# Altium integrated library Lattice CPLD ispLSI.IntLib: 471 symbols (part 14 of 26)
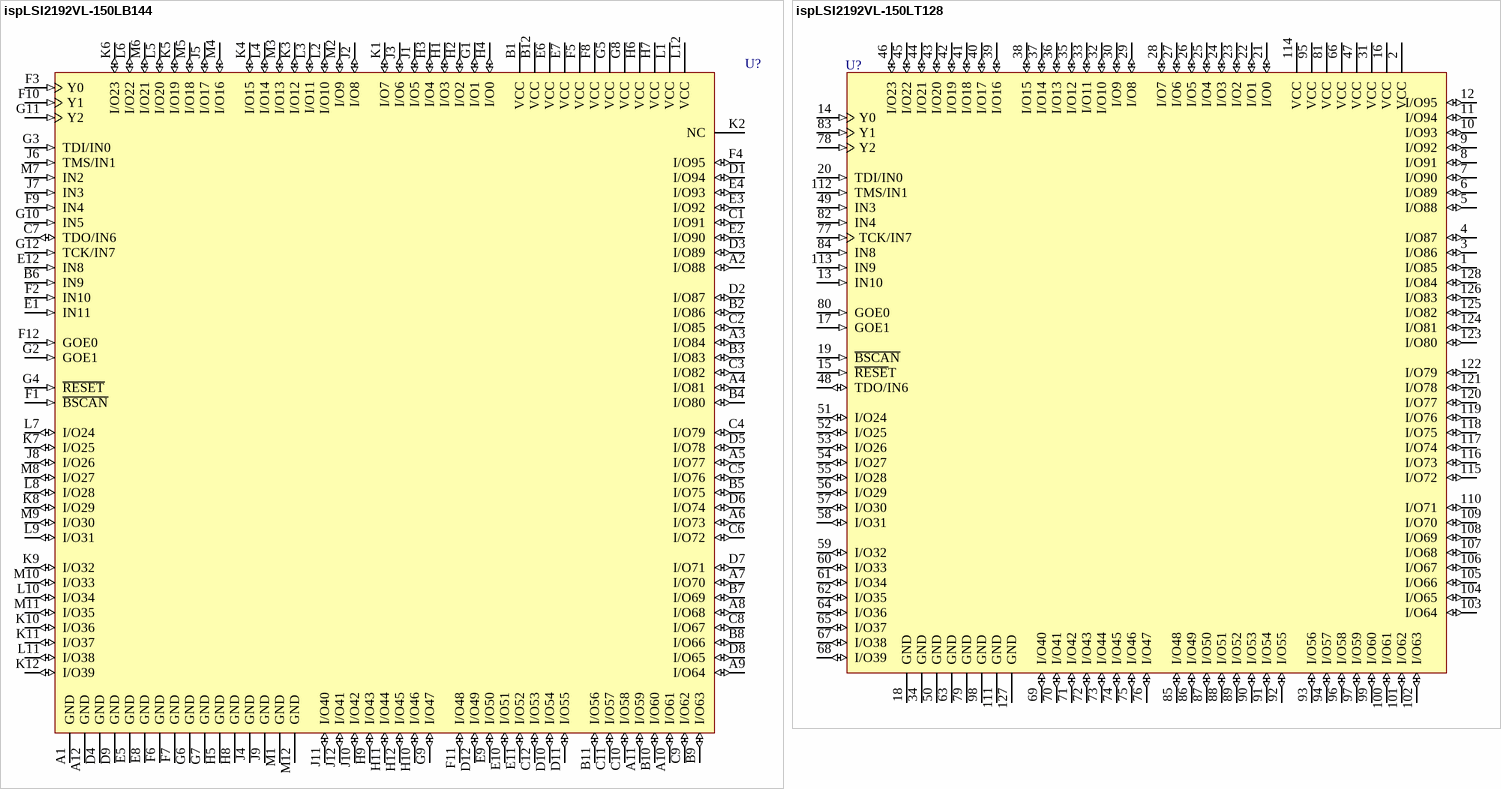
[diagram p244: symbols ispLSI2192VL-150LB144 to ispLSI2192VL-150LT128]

## ispLSI2192VL-150LB144
designator U?
2.5V In-System Programmable SuperFAST High Density PLD
footprint fpBGA144 (BGA, 144-Leads, Body 13x13mm, Pitch 1mm)
3D model 2192VL-fpBGA144 (144-Ball Fine Pitch Ball Grid Array (fpBGA144))
pins: A1 GND (power), A2 I/O88 (io), A3 I/O84 (io), A4 I/O81 (io), A5 I/O77 (io), A6 I/O73 (io), A7 I/O70 (io), A8 I/O68 (io), A9 I/O64 (io), A10 I/O61 (io), A11 I/O59 (io), A12 GND (power), B1 VCC (power), B2 I/O86 (io), B3 I/O83 (io), B4 I/O80 (io), B5 I/O75 (io), B6 IN9 (in), B7 I/O69 (io), B8 I/O66 (io), B9 I/O63 (io), B10 I/O60 (io), B11 I/O56 (io), B12 VCC (power), C1 I/O91 (io), C2 I/O85 (io), C3 I/O82 (io), C4 I/O79 (io), C5 I/O76 (io), C6 I/O72 (io), C7 TDO/IN6 (io), C8 I/O67 (io), C9 I/O62 (io), C10 I/O58 (io), C11 I/O57 (io), C12 I/O53 (io), D1 I/O94 (io), D2 I/O87 (io), D3 I/O89 (io), D4 GND (power), D5 I/O78 (io), D6 I/O74 (io), D7 I/O71 (io), D8 I/O65 (io), D9 GND (power), D10 I/O54 (io), D11 I/O55 (io), D12 I/O49 (io), E1 IN11 (in), E2 I/O90 (io), E3 I/O92 (io), E4 I/O93 (io), E5 GND (power), E6 VCC (power), E7 VCC (power), E8 GND (power), E9 I/O50 (io), E10 I/O51 (io), E11 I/O52 (io), E12 IN8 (in), F1 ~{BSCAN} (in), F2 IN10 (in), F3 Y0 (in), F4 I/O95 (io), F5 VCC (power), F6 GND (power), F7 GND (power), F8 VCC (power), F9 IN4 (in), F10 Y1 (in), F11 I/O48 (io), F12 GOE0 (in), G1 I/O1 (io), G2 GOE1 (in), G3 TDI/IN0 (in), G4 ~{RESET} (in), G5 VCC (power), G6 GND (power), G7 GND (power), G8 VCC (power), G9 I/O47 (io), G10 IN5 (in), G11 Y2 (in), G12 TCK/IN7 (in), H1 I/O3 (io), H2 I/O2 (io), H3 I/O4 (io), H4 I/O0 (io), H5 GND (power), H6 VCC (power), H7 VCC (power), H8 GND (power), H9 I/O43 (io), H10 I/O46 (io), H11 I/O44 (io), H12 I/O45 (io), J1 I/O5 (io), J2 I/O8 (io), J3 I/O6 (io), J4 GND (power), J5 I/O17 (io), J6 TMS/IN1 (in), J7 IN3 (in), J8 I/O26 (io), J9 GND (power), J10 I/O42 (io), J11 I/O40 (io), J12 I/O41 (io), K1 I/O7 (io), K2 NC, K3 I/O12 (io), K4 I/O15 (io), K5 I/O19 (io), K6 I/O23 (io), K7 I/O25 (io), K8 I/O29 (io), K9 I/O32 (io), K10 I/O36 (io), K11 I/O37 (io), K12 I/O39 (io), L1 VCC (power), L2 I/O10 (io), L3 I/O11 (io), L4 I/O14 (io), L5 I/O20 (io), L6 I/O22 (io), L7 I/O24 (io), L8 I/O28 (io), L9 I/O31 (io), L10 I/O34 (io), L11 I/O38 (io), L12 VCC (power), M1 GND (power), M2 I/O9 (io), M3 I/O13 (io), M4 I/O16 (io), M5 I/O18 (io), M6 I/O21 (io), M7 IN2 (in), M8 I/O27 (io), M9 I/O30 (io), M10 I/O33 (io), M11 I/O35 (io), M12 GND (power)

## ispLSI2192VL-150LT128
designator U?
2.5V In-System Programmable SuperFAST High Density PLD
footprint TQFP128_N (Thin QFP, 128-Leads, Body 14x14mm, Pitch 0.4mm, IPC Medium Density)
footprint TQFP128_L (Thin QFP, 128-Leads, Body 14x14mm, Pitch 0.4mm, IPC High Density)
footprint TQFP128_M (Thin QFP, 128-Leads, Body 14x14mm, Pitch 0.4mm, IPC Low Density)
3D model 2192VL-TQFP128 (128-Pin Thin Quad Flat Pack 0.4 mm Pitch)
pins: 1 I/O85 (io), 2 VCC (power), 3 I/O86 (io), 4 I/O87 (io), 5 I/O88 (io), 6 I/O89 (io), 7 I/O90 (io), 8 I/O91 (io), 9 I/O92 (io), 10 I/O93 (io), 11 I/O94 (io), 12 I/O95 (io), 13 IN10 (in), 14 Y0 (in), 15 ~{RESE}T (in), 16 VCC (power), 17 GOE1 (in), 18 GND (power), 19 ~{BSCAN} (in), 20 TDI/IN0 (in), 21 I/O0 (io), 22 I/O1 (io), 23 I/O2 (io), 24 I/O3 (io), 25 I/O4 (io), 26 I/O5 (io), 27 I/O6 (io), 28 I/O7 (io), 29 I/O8 (io), 30 I/O9 (io), 31 VCC (power), 32 I/O10 (io), 33 I/O11 (io), 34 GND (power), 35 I/O12 (io), 36 I/O13 (io), 37 I/O14 (io), 38 I/O15 (io), 39 I/O16 (io), 40 I/O17 (io), 41 I/O18 (io), 42 I/O19 (io), 43 I/O20 (io), 44 I/O21 (io), 45 I/O22 (io), 46 I/O23 (io), 47 VCC (power), 48 TDO/IN6 (io), 49 IN3 (in), 50 GND (power), 51 I/O24 (io), 52 I/O25 (io), 53 I/O26 (io), 54 I/O27 (io), 55 I/O28 (io), 56 I/O29 (io), 57 I/O30 (io), 58 I/O31 (io), 59 I/O32 (io), 60 I/O33 (io), 61 I/O34 (io), 62 I/O35 (io), 63 GND (power), 64 I/O36 (io), 65 I/O37 (io), 66 VCC (power), 67 I/O38 (io), 68 I/O39 (io), 69 I/O40 (io), 70 I/O41 (io), 71 I/O42 (io), 72 I/O43 (io), 73 I/O44 (io), 74 I/O45 (io), 75 I/O46 (io), 76 I/O47 (io), 77 TCK/IN7 (in), 78 Y2 (in), 79 GND (power), 80 GOE0 (in), 81 VCC (power), 82 IN4 (in), 83 Y1 (in), 84 IN8 (in), 85 I/O48 (io), 86 I/O49 (io), 87 I/O50 (io), 88 I/O51 (io), 89 I/O52 (io), 90 I/O53 (io), 91 I/O54 (io), 92 I/O55 (io), 93 I/O56 (io), 94 I/O57 (io), 95 VCC (power), 96 I/O58 (io), 97 I/O59 (io), 98 GND (power), 99 I/O60 (io), 100 I/O61 (io), 101 I/O62 (io), 102 I/O63 (io), 103 I/O64 (io), 104 I/O65 (io), 105 I/O66 (io), 106 I/O67 (io), 107 I/O68 (io), 108 I/O69 (io), 109 I/O70 (io), 110 I/O71 (io), 111 GND (power), 112 TMS/IN1 (in), 113 IN9 (in), 114 VCC (power), 115 I/O72 (io), 116 I/O73 (io), 117 I/O74 (io), 118 I/O75 (io), 119 I/O76 (io), 120 I/O77 (io), 121 I/O78 (io), 122 I/O79 (io), 123 I/O80 (io), 124 I/O81 (io), 125 I/O82 (io), 126 I/O83 (io), 127 GND (power), 128 I/O84 (io)

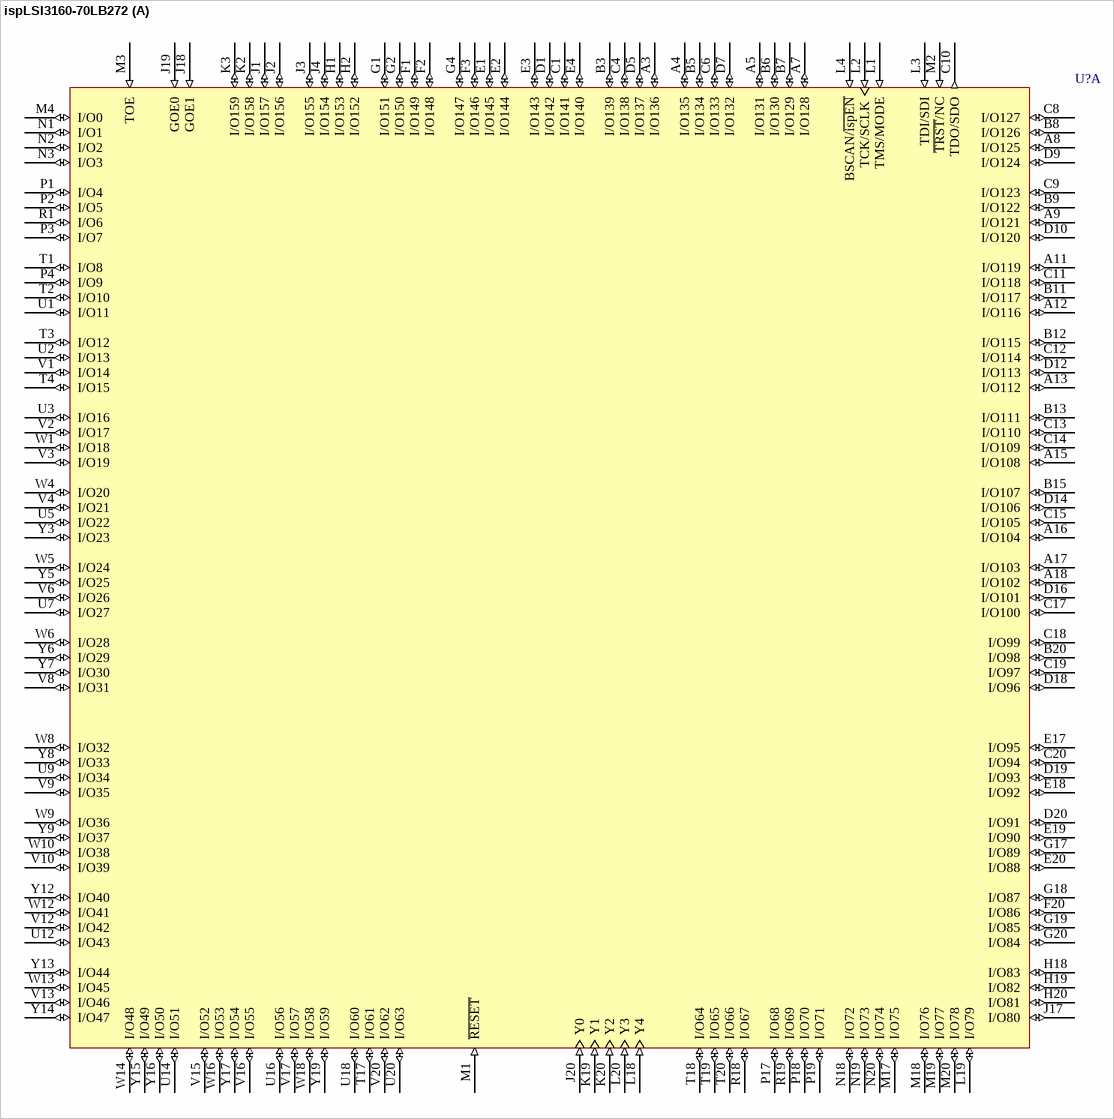
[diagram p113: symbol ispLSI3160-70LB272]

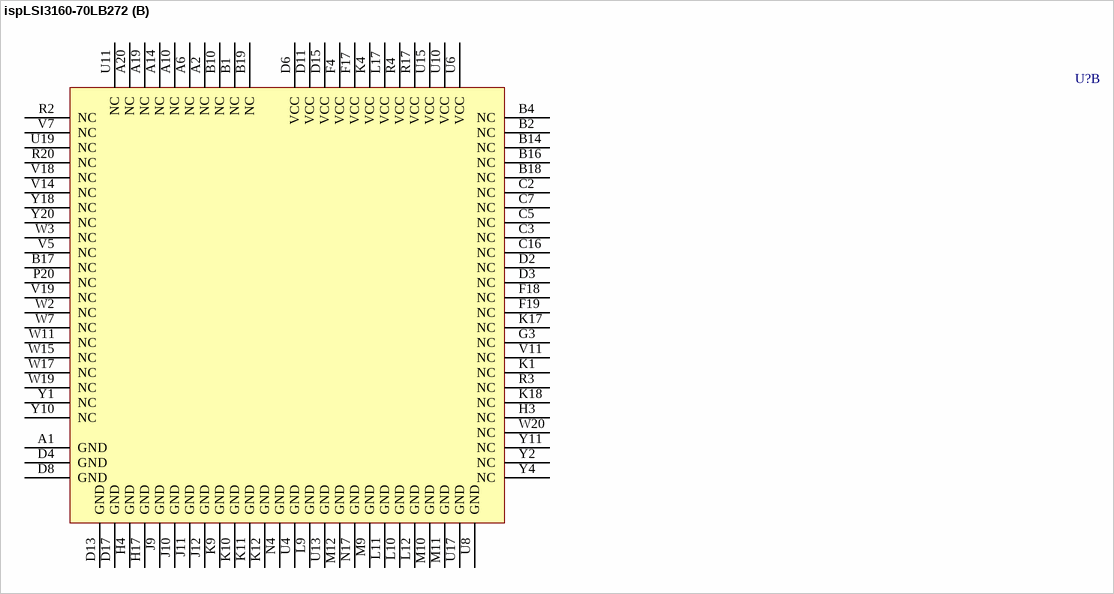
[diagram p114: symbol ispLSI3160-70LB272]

## ispLSI3160-70LB272
designator U?
In-System Programmable High-Density PLD
footprint BGA272 (BGA, 272-Leads, Body 27x27mm, Pitch 1.27mm)
3D model 3160-BGA272 (272-Ball Ball Grid Array (BGA272))
part A pins: A3 I/O136 (io), A4 I/O135 (io), A5 I/O131 (io), A7 I/O128 (io), A8 I/O125 (io), A9 I/O121 (io), A11 I/O119 (io), A12 I/O116 (io), A13 I/O112 (io), A15 I/O108 (io), A16 I/O104 (io), A17 I/O103 (io), A18 I/O102 (io), B3 I/O139 (io), B5 I/O134 (io), B6 I/O130 (io), B7 I/O129 (io), B8 I/O126 (io), B9 I/O122 (io), B11 I/O117 (io), B12 I/O115 (io), B13 I/O111 (io), B15 I/O107 (io), B20 I/O98 (io), C1 I/O141 (io), C4 I/O138 (io), C6 I/O133 (io), C8 I/O127 (io), C9 I/O123 (io), C10 TDO/SDO (out), C11 I/O118 (io), C12 I/O114 (io), C13 I/O110 (io), C14 I/O109 (io), C15 I/O105 (io), C17 I/O100 (io), C18 I/O99 (io), C19 I/O97 (io), C20 I/O94 (io), D1 I/O142 (io), D5 I/O137 (io), D7 I/O132 (io), D9 I/O124 (io), D10 I/O120 (io), D12 I/O113 (io), D14 I/O106 (io), D16 I/O101 (io), D18 I/O96 (io), D19 I/O93 (io), D20 I/O91 (io), E1 I/O145 (io), E2 I/O144 (io), E3 I/O143 (io), E4 I/O140 (io), E17 I/O95 (io), E18 I/O92 (io), E19 I/O90 (io), E20 I/O88 (io), F1 I/O149 (io), F2 I/O148 (io), F3 I/O146 (io), F20 I/O86 (io), G1 I/O151 (io), G2 I/O150 (io), G4 I/O147 (io), G17 I/O89 (io), G18 I/O87 (io), G19 I/O85 (io), G20 I/O84 (io), H1 I/O153 (io), H2 I/O152 (io), H18 I/O83 (io), H19 I/O82 (io), H20 I/O81 (io), J1 I/O157 (io), J2 I/O156 (io), J3 I/O155 (io), J4 I/O154 (io), J17 I/O80 (io), J18 GOE1 (in), J19 GOE0 (in), J20 Y0 (in), K2 I/O158 (io), K3 I/O159 (io), K19 Y1 (in), K20 Y2 (in), L1 TMS/MODE (in), L2 TCK/SCLK (in), L3 TDI/SDI (in), L4 BSCAN/~{ispEN} (in), L18 Y4 (in), L19 I/O79 (io), L20 Y3 (in), M1 ~{RESET} (in), M2 ~{TRST}/NC (in), M3 TOE (in), M4 I/O0 (io), M17 I/O75 (io), M18 I/O76 (io), M19 I/O77 (io), M20 I/O78 (io), N1 I/O1 (io), N2 I/O2 (io), N3 I/O3 (io), N18 I/O72 (io), N19 I/O73 (io), N20 I/O74 (io), P1 I/O4 (io), P2 I/O5 (io), P3 I/O7 (io), P4 I/O9 (io), P17 I/O68 (io), P18 I/O70 (io), P19 I/O71 (io), R1 I/O6 (io), R18 I/O67 (io), R19 I/O69 (io), T1 I/O8 (io), T2 I/O10 (io), T3 I/O12 (io), T4 I/O15 (io), T17 I/O61 (io), T18 I/O64 (io), T19 I/O65 (io), T20 I/O66 (io), U1 I/O11 (io), U2 I/O13 (io), U3 I/O16 (io), U5 I/O22 (io), U7 I/O27 (io), U9 I/O34 (io), U12 I/O43 (io), U14 I/O51 (io), U16 I/O56 (io), U18 I/O60 (io), U20 I/O63 (io), V1 I/O14 (io), V2 I/O17 (io), V3 I/O19 (io), V4 I/O21 (io), V6 I/O26 (io), V8 I/O31 (io), V9 I/O35 (io), V10 I/O39 (io), V12 I/O42 (io), V13 I/O46 (io), V15 I/O52 (io), V16 I/O55 (io), V17 I/O57 (io), V20 I/O62 (io), W1 I/O18 (io), W4 I/O20 (io), W5 I/O24 (io), W6 I/O28 (io), W8 I/O32 (io), W9 I/O36 (io), W10 I/O38 (io), W12 I/O41 (io), W13 I/O45 (io), W14 I/O48 (io), W16 I/O53 (io), W18 I/O58 (io), Y3 I/O23 (io), Y5 I/O25 (io), Y6 I/O29 (io), Y7 I/O30 (io), Y8 I/O33 (io), Y9 I/O37 (io), Y12 I/O40 (io), Y13 I/O44 (io), Y14 I/O47 (io), Y15 I/O49 (io), Y16 I/O50 (io), Y17 I/O54 (io), Y19 I/O59 (io)
part B pins: A1 GND (power), A2 NC, A6 NC, A10 NC, A14 NC, A19 NC, A20 NC, B1 NC, B2 NC, B4 NC, B10 NC, B14 NC, B16 NC, B17 NC, B18 NC, B19 NC, C2 NC, C3 NC, C5 NC, C7 NC, C16 NC, D2 NC, D3 NC, D4 GND (power), D6 VCC (power), D8 GND (power), D11 VCC (power), D13 GND (power), D15 VCC (power), D17 GND (power), F4 VCC (power), F17 VCC (power), F18 NC, F19 NC, G3 NC, H3 NC, H4 GND (power), H17 GND (power), J9 GND (power), J10 GND (power), J11 GND (power), J12 GND (power), K1 NC, K4 VCC (power), K9 GND (power), K10 GND (power), K11 GND (power), K12 GND (power), K17 NC, K18 NC, L9 GND (power), L10 GND (power), L11 GND (power), L12 GND (power), L17 VCC (power), M9 GND (power), M10 GND (power), M11 GND (power), M12 GND (power), N4 GND (power), N17 GND (power), P20 NC, R2 NC, R3 NC, R4 VCC (power), R17 VCC (power), R20 NC, U4 GND (power), U6 VCC (power), U8 GND (power), U10 VCC (power), U11 NC, U13 GND (power), U15 VCC (power), U17 GND (power), U19 NC, V5 NC, V7 NC, V11 NC, V14 NC, V18 NC, V19 NC, W2 NC, W3 NC, W7 NC, W11 NC, W15 NC, W17 NC, W19 NC, W20 NC, Y1 NC, Y2 NC, Y4 NC, Y10 NC, Y11 NC, Y18 NC, Y20 NC

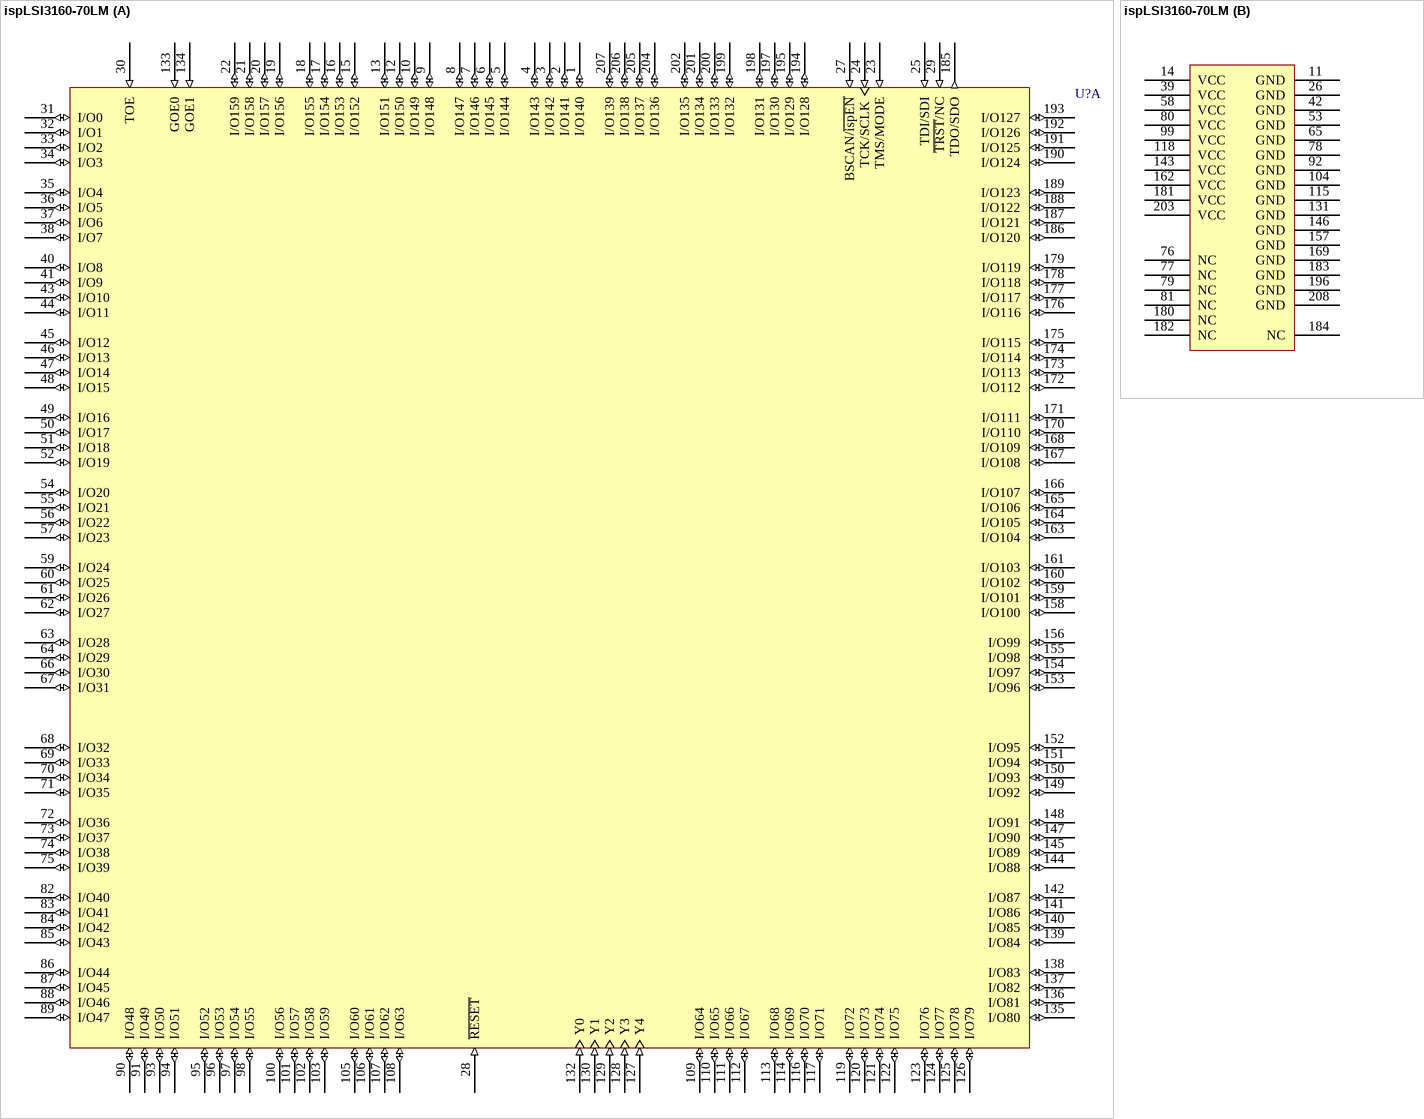
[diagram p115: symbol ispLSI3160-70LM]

## ispLSI3160-70LM
designator U?
In-System Programmable High-Density PLD
footprint MQFP208_N (Shrink QFP, 208-Leads, Body 27.7x27.7mm, Pitch 0.5mm, IPC Medium Density)
footprint MQFP208_L (Shrink QFP, 208-Leads, Body 27.7x27.7mm, Pitch 0.5mm, IPC High Density)
footprint MQFP208_M (Shrink QFP, 208-Leads, Body 27.7x27.7mm, Pitch 0.5mm, IPC Low Density)
3D model 3160-MQFP208 (208-Pin Shrink Quad Flat Pack 0.5 mm Pitch)
part A pins: 1 I/O140 (io), 2 I/O141 (io), 3 I/O142 (io), 4 I/O143 (io), 5 I/O144 (io), 6 I/O145 (io), 7 I/O146 (io), 8 I/O147 (io), 9 I/O148 (io), 10 I/O149 (io), 12 I/O150 (io), 13 I/O151 (io), 15 I/O152 (io), 16 I/O153 (io), 17 I/O154 (io), 18 I/O155 (io), 19 I/O156 (io), 20 I/O157 (io), 21 I/O158 (io), 22 I/O159 (io), 23 TMS/MODE (in), 24 TCK/SCLK (in), 25 TDI/SDI (in), 27 BSCAN/~{ispEN} (in), 28 ~{RESET} (in), 29 ~{TRST}/NC (in), 30 TOE (in), 31 I/O0 (io), 32 I/O1 (io), 33 I/O2 (io), 34 I/O3 (io), 35 I/O4 (io), 36 I/O5 (io), 37 I/O6 (io), 38 I/O7 (io), 40 I/O8 (io), 41 I/O9 (io), 43 I/O10 (io), 44 I/O11 (io), 45 I/O12 (io), 46 I/O13 (io), 47 I/O14 (io), 48 I/O15 (io), 49 I/O16 (io), 50 I/O17 (io), 51 I/O18 (io), 52 I/O19 (io), 54 I/O20 (io), 55 I/O21 (io), 56 I/O22 (io), 57 I/O23 (io), 59 I/O24 (io), 60 I/O25 (io), 61 I/O26 (io), 62 I/O27 (io), 63 I/O28 (io), 64 I/O29 (io), 66 I/O30 (io), 67 I/O31 (io), 68 I/O32 (io), 69 I/O33 (io), 70 I/O34 (io), 71 I/O35 (io), 72 I/O36 (io), 73 I/O37 (io), 74 I/O38 (io), 75 I/O39 (io), 82 I/O40 (io), 83 I/O41 (io), 84 I/O42 (io), 85 I/O43 (io), 86 I/O44 (io), 87 I/O45 (io), 88 I/O46 (io), 89 I/O47 (io), 90 I/O48 (io), 91 I/O49 (io), 93 I/O50 (io), 94 I/O51 (io), 95 I/O52 (io), 96 I/O53 (io), 97 I/O54 (io), 98 I/O55 (io), 100 I/O56 (io), 101 I/O57 (io), 102 I/O58 (io), 103 I/O59 (io), 105 I/O60 (io), 106 I/O61 (io), 107 I/O62 (io), 108 I/O63 (io), 109 I/O64 (io), 110 I/O65 (io), 111 I/O66 (io), 112 I/O67 (io), 113 I/O68 (io), 114 I/O69 (io), 116 I/O70 (io), 117 I/O71 (io), 119 I/O72 (io), 120 I/O73 (io), 121 I/O74 (io), 122 I/O75 (io), 123 I/O76 (io), 124 I/O77 (io), 125 I/O78 (io), 126 I/O79 (io), 127 Y4 (in), 128 Y3 (in), 129 Y2 (in), 130 Y1 (in), 132 Y0 (in), 133 GOE0 (in), 134 GOE1 (in), 135 I/O80 (io), 136 I/O81 (io), 137 I/O82 (io), 138 I/O83 (io), 139 I/O84 (io), 140 I/O85 (io), 141 I/O86 (io), 142 I/O87 (io), 144 I/O88 (io), 145 I/O89 (io), 147 I/O90 (io), 148 I/O91 (io), 149 I/O92 (io), 150 I/O93 (io), 151 I/O94 (io), 152 I/O95 (io), 153 I/O96 (io), 154 I/O97 (io), 155 I/O98 (io), 156 I/O99 (io), 158 I/O100 (io), 159 I/O101 (io), 160 I/O102 (io), 161 I/O103 (io), 163 I/O104 (io), 164 I/O105 (io), 165 I/O106 (io), 166 I/O107 (io), 167 I/O108 (io), 168 I/O109 (io), 170 I/O110 (io), 171 I/O111 (io), 172 I/O112 (io), 173 I/O113 (io), 174 I/O114 (io), 175 I/O115 (io), 176 I/O116 (io), 177 I/O117 (io), 178 I/O118 (io), 179 I/O119 (io), 185 TDO/SDO (out), 186 I/O120 (io), 187 I/O121 (io), 188 I/O122 (io), 189 I/O123 (io), 190 I/O124 (io), 191 I/O125 (io), 192 I/O126 (io), 193 I/O127 (io), 194 I/O128 (io), 195 I/O129 (io), 197 I/O130 (io), 198 I/O131 (io), 199 I/O132 (io), 200 I/O133 (io), 201 I/O134 (io), 202 I/O135 (io), 204 I/O136 (io), 205 I/O137 (io), 206 I/O138 (io), 207 I/O139 (io)
part B pins: 11 GND (power), 14 VCC (power), 26 GND (power), 39 VCC (power), 42 GND (power), 53 GND (power), 58 VCC (power), 65 GND (power), 76 NC, 77 NC, 78 GND (power), 79 NC, 80 VCC (power), 81 NC, 92 GND (power), 99 VCC (power), 104 GND (power), 115 GND (power), 118 VCC (power), 131 GND (power), 143 VCC (power), 146 GND (power), 157 GND (power), 162 VCC (power), 169 GND (power), 180 NC, 181 VCC (power), 182 NC, 183 GND (power), 184 NC, 196 GND (power), 203 VCC (power), 208 GND (power)

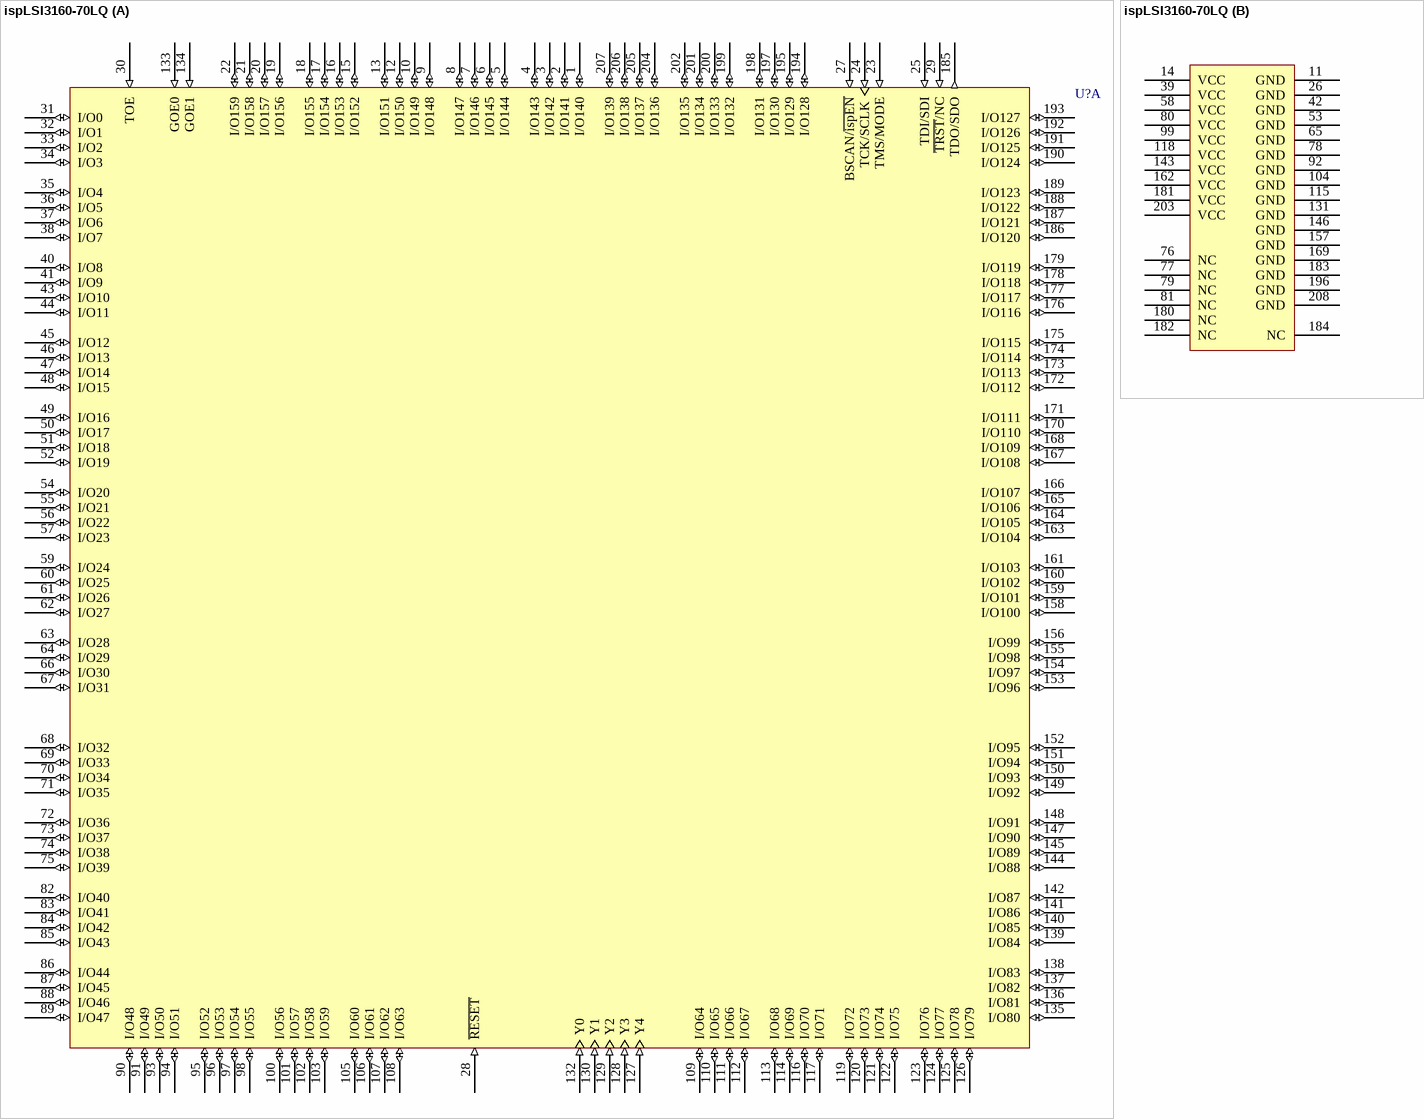
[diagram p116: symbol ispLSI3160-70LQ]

## ispLSI3160-70LQ
designator U?
In-System Programmable High-Density PLD
footprint PQFP208_N (Shrink QFP, 208-Leads, Body 28x28mm, Pitch 0.5mm, IPC Medium Density)
footprint PQFP208_L (Shrink QFP, 208-Leads, Body 28x28mm, Pitch 0.5mm, IPC High Density)
footprint PQFP208_M (Shrink QFP, 208-Leads, Body 28x28mm, Pitch 0.5mm, IPC Low Density)
3D model 3160-PQFP208 (208-Pin Plastic Quad Flat Pack (PQFP208))
part A pins: 1 I/O140 (io), 2 I/O141 (io), 3 I/O142 (io), 4 I/O143 (io), 5 I/O144 (io), 6 I/O145 (io), 7 I/O146 (io), 8 I/O147 (io), 9 I/O148 (io), 10 I/O149 (io), 12 I/O150 (io), 13 I/O151 (io), 15 I/O152 (io), 16 I/O153 (io), 17 I/O154 (io), 18 I/O155 (io), 19 I/O156 (io), 20 I/O157 (io), 21 I/O158 (io), 22 I/O159 (io), 23 TMS/MODE (in), 24 TCK/SCLK (in), 25 TDI/SDI (in), 27 BSCAN/~{ispEN} (in), 28 ~{RESET} (in), 29 ~{TRST}/NC (in), 30 TOE (in), 31 I/O0 (io), 32 I/O1 (io), 33 I/O2 (io), 34 I/O3 (io), 35 I/O4 (io), 36 I/O5 (io), 37 I/O6 (io), 38 I/O7 (io), 40 I/O8 (io), 41 I/O9 (io), 43 I/O10 (io), 44 I/O11 (io), 45 I/O12 (io), 46 I/O13 (io), 47 I/O14 (io), 48 I/O15 (io), 49 I/O16 (io), 50 I/O17 (io), 51 I/O18 (io), 52 I/O19 (io), 54 I/O20 (io), 55 I/O21 (io), 56 I/O22 (io), 57 I/O23 (io), 59 I/O24 (io), 60 I/O25 (io), 61 I/O26 (io), 62 I/O27 (io), 63 I/O28 (io), 64 I/O29 (io), 66 I/O30 (io), 67 I/O31 (io), 68 I/O32 (io), 69 I/O33 (io), 70 I/O34 (io), 71 I/O35 (io), 72 I/O36 (io), 73 I/O37 (io), 74 I/O38 (io), 75 I/O39 (io), 82 I/O40 (io), 83 I/O41 (io), 84 I/O42 (io), 85 I/O43 (io), 86 I/O44 (io), 87 I/O45 (io), 88 I/O46 (io), 89 I/O47 (io), 90 I/O48 (io), 91 I/O49 (io), 93 I/O50 (io), 94 I/O51 (io), 95 I/O52 (io), 96 I/O53 (io), 97 I/O54 (io), 98 I/O55 (io), 100 I/O56 (io), 101 I/O57 (io), 102 I/O58 (io), 103 I/O59 (io), 105 I/O60 (io), 106 I/O61 (io), 107 I/O62 (io), 108 I/O63 (io), 109 I/O64 (io), 110 I/O65 (io), 111 I/O66 (io), 112 I/O67 (io), 113 I/O68 (io), 114 I/O69 (io), 116 I/O70 (io), 117 I/O71 (io), 119 I/O72 (io), 120 I/O73 (io), 121 I/O74 (io), 122 I/O75 (io), 123 I/O76 (io), 124 I/O77 (io), 125 I/O78 (io), 126 I/O79 (io), 127 Y4 (in), 128 Y3 (in), 129 Y2 (in), 130 Y1 (in), 132 Y0 (in), 133 GOE0 (in), 134 GOE1 (in), 135 I/O80 (io), 136 I/O81 (io), 137 I/O82 (io), 138 I/O83 (io), 139 I/O84 (io), 140 I/O85 (io), 141 I/O86 (io), 142 I/O87 (io), 144 I/O88 (io), 145 I/O89 (io), 147 I/O90 (io), 148 I/O91 (io), 149 I/O92 (io), 150 I/O93 (io), 151 I/O94 (io), 152 I/O95 (io), 153 I/O96 (io), 154 I/O97 (io), 155 I/O98 (io), 156 I/O99 (io), 158 I/O100 (io), 159 I/O101 (io), 160 I/O102 (io), 161 I/O103 (io), 163 I/O104 (io), 164 I/O105 (io), 165 I/O106 (io), 166 I/O107 (io), 167 I/O108 (io), 168 I/O109 (io), 170 I/O110 (io), 171 I/O111 (io), 172 I/O112 (io), 173 I/O113 (io), 174 I/O114 (io), 175 I/O115 (io), 176 I/O116 (io), 177 I/O117 (io), 178 I/O118 (io), 179 I/O119 (io), 185 TDO/SDO (out), 186 I/O120 (io), 187 I/O121 (io), 188 I/O122 (io), 189 I/O123 (io), 190 I/O124 (io), 191 I/O125 (io), 192 I/O126 (io), 193 I/O127 (io), 194 I/O128 (io), 195 I/O129 (io), 197 I/O130 (io), 198 I/O131 (io), 199 I/O132 (io), 200 I/O133 (io), 201 I/O134 (io), 202 I/O135 (io), 204 I/O136 (io), 205 I/O137 (io), 206 I/O138 (io), 207 I/O139 (io)
part B pins: 11 GND (power), 14 VCC (power), 26 GND (power), 39 VCC (power), 42 GND (power), 53 GND (power), 58 VCC (power), 65 GND (power), 76 NC, 77 NC, 78 GND (power), 79 NC, 80 VCC (power), 81 NC, 92 GND (power), 99 VCC (power), 104 GND (power), 115 GND (power), 118 VCC (power), 131 GND (power), 143 VCC (power), 146 GND (power), 157 GND (power), 162 VCC (power), 169 GND (power), 180 NC, 181 VCC (power), 182 NC, 183 GND (power), 184 NC, 196 GND (power), 203 VCC (power), 208 GND (power)

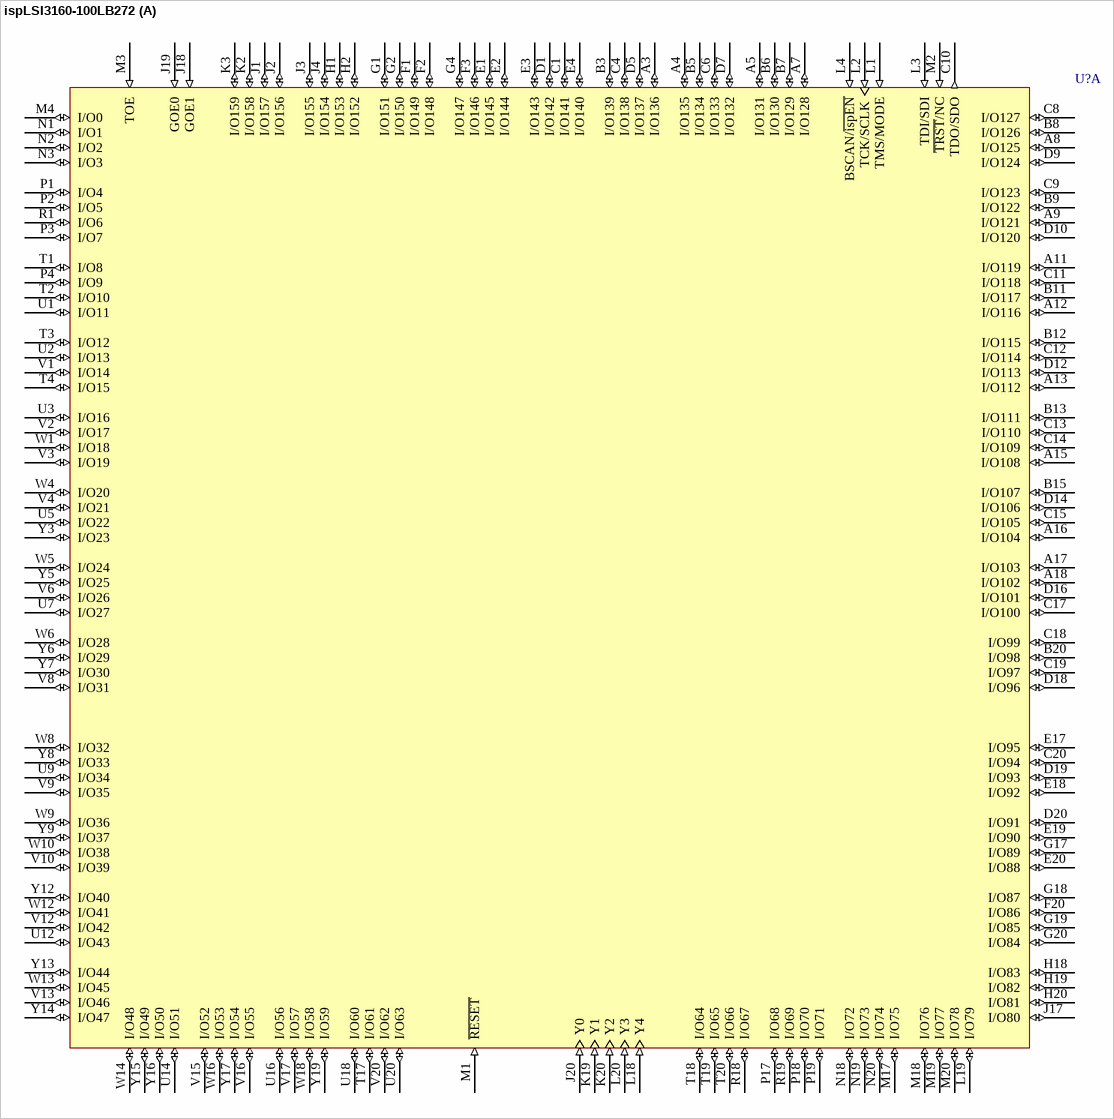
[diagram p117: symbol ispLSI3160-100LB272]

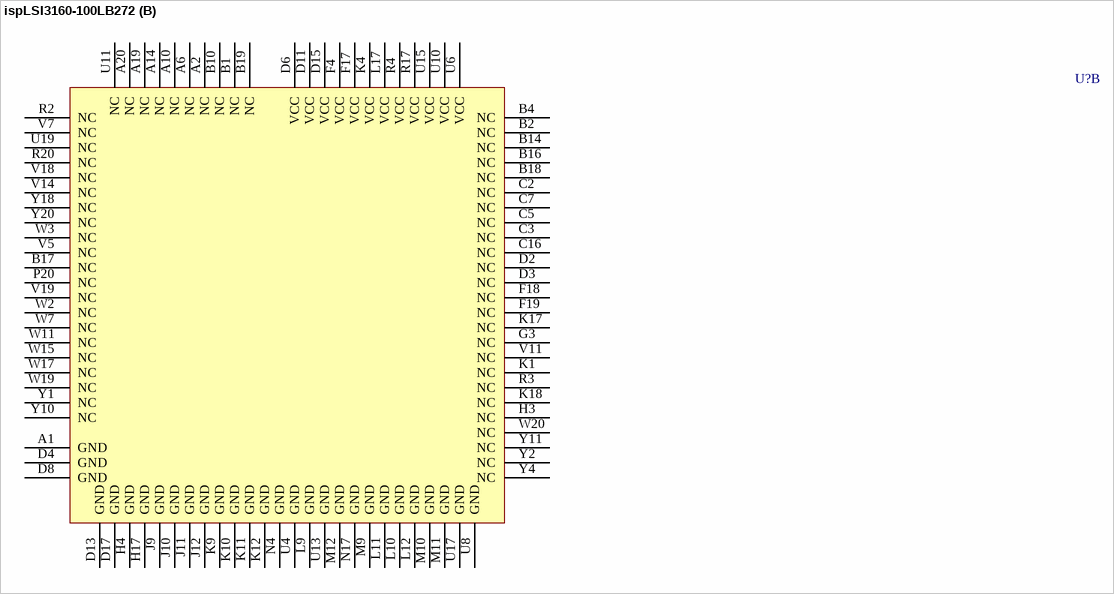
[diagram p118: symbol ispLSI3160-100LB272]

## ispLSI3160-100LB272
designator U?
In-System Programmable High-Density PLD
footprint BGA272 (BGA, 272-Leads, Body 27x27mm, Pitch 1.27mm)
3D model 3160-BGA272 (272-Ball Ball Grid Array (BGA272))
part A pins: A3 I/O136 (io), A4 I/O135 (io), A5 I/O131 (io), A7 I/O128 (io), A8 I/O125 (io), A9 I/O121 (io), A11 I/O119 (io), A12 I/O116 (io), A13 I/O112 (io), A15 I/O108 (io), A16 I/O104 (io), A17 I/O103 (io), A18 I/O102 (io), B3 I/O139 (io), B5 I/O134 (io), B6 I/O130 (io), B7 I/O129 (io), B8 I/O126 (io), B9 I/O122 (io), B11 I/O117 (io), B12 I/O115 (io), B13 I/O111 (io), B15 I/O107 (io), B20 I/O98 (io), C1 I/O141 (io), C4 I/O138 (io), C6 I/O133 (io), C8 I/O127 (io), C9 I/O123 (io), C10 TDO/SDO (out), C11 I/O118 (io), C12 I/O114 (io), C13 I/O110 (io), C14 I/O109 (io), C15 I/O105 (io), C17 I/O100 (io), C18 I/O99 (io), C19 I/O97 (io), C20 I/O94 (io), D1 I/O142 (io), D5 I/O137 (io), D7 I/O132 (io), D9 I/O124 (io), D10 I/O120 (io), D12 I/O113 (io), D14 I/O106 (io), D16 I/O101 (io), D18 I/O96 (io), D19 I/O93 (io), D20 I/O91 (io), E1 I/O145 (io), E2 I/O144 (io), E3 I/O143 (io), E4 I/O140 (io), E17 I/O95 (io), E18 I/O92 (io), E19 I/O90 (io), E20 I/O88 (io), F1 I/O149 (io), F2 I/O148 (io), F3 I/O146 (io), F20 I/O86 (io), G1 I/O151 (io), G2 I/O150 (io), G4 I/O147 (io), G17 I/O89 (io), G18 I/O87 (io), G19 I/O85 (io), G20 I/O84 (io), H1 I/O153 (io), H2 I/O152 (io), H18 I/O83 (io), H19 I/O82 (io), H20 I/O81 (io), J1 I/O157 (io), J2 I/O156 (io), J3 I/O155 (io), J4 I/O154 (io), J17 I/O80 (io), J18 GOE1 (in), J19 GOE0 (in), J20 Y0 (in), K2 I/O158 (io), K3 I/O159 (io), K19 Y1 (in), K20 Y2 (in), L1 TMS/MODE (in), L2 TCK/SCLK (in), L3 TDI/SDI (in), L4 BSCAN/~{ispEN} (in), L18 Y4 (in), L19 I/O79 (io), L20 Y3 (in), M1 ~{RESET} (in), M2 ~{TRST}/NC (in), M3 TOE (in), M4 I/O0 (io), M17 I/O75 (io), M18 I/O76 (io), M19 I/O77 (io), M20 I/O78 (io), N1 I/O1 (io), N2 I/O2 (io), N3 I/O3 (io), N18 I/O72 (io), N19 I/O73 (io), N20 I/O74 (io), P1 I/O4 (io), P2 I/O5 (io), P3 I/O7 (io), P4 I/O9 (io), P17 I/O68 (io), P18 I/O70 (io), P19 I/O71 (io), R1 I/O6 (io), R18 I/O67 (io), R19 I/O69 (io), T1 I/O8 (io), T2 I/O10 (io), T3 I/O12 (io), T4 I/O15 (io), T17 I/O61 (io), T18 I/O64 (io), T19 I/O65 (io), T20 I/O66 (io), U1 I/O11 (io), U2 I/O13 (io), U3 I/O16 (io), U5 I/O22 (io), U7 I/O27 (io), U9 I/O34 (io), U12 I/O43 (io), U14 I/O51 (io), U16 I/O56 (io), U18 I/O60 (io), U20 I/O63 (io), V1 I/O14 (io), V2 I/O17 (io), V3 I/O19 (io), V4 I/O21 (io), V6 I/O26 (io), V8 I/O31 (io), V9 I/O35 (io), V10 I/O39 (io), V12 I/O42 (io), V13 I/O46 (io), V15 I/O52 (io), V16 I/O55 (io), V17 I/O57 (io), V20 I/O62 (io), W1 I/O18 (io), W4 I/O20 (io), W5 I/O24 (io), W6 I/O28 (io), W8 I/O32 (io), W9 I/O36 (io), W10 I/O38 (io), W12 I/O41 (io), W13 I/O45 (io), W14 I/O48 (io), W16 I/O53 (io), W18 I/O58 (io), Y3 I/O23 (io), Y5 I/O25 (io), Y6 I/O29 (io), Y7 I/O30 (io), Y8 I/O33 (io), Y9 I/O37 (io), Y12 I/O40 (io), Y13 I/O44 (io), Y14 I/O47 (io), Y15 I/O49 (io), Y16 I/O50 (io), Y17 I/O54 (io), Y19 I/O59 (io)
part B pins: A1 GND (power), A2 NC, A6 NC, A10 NC, A14 NC, A19 NC, A20 NC, B1 NC, B2 NC, B4 NC, B10 NC, B14 NC, B16 NC, B17 NC, B18 NC, B19 NC, C2 NC, C3 NC, C5 NC, C7 NC, C16 NC, D2 NC, D3 NC, D4 GND (power), D6 VCC (power), D8 GND (power), D11 VCC (power), D13 GND (power), D15 VCC (power), D17 GND (power), F4 VCC (power), F17 VCC (power), F18 NC, F19 NC, G3 NC, H3 NC, H4 GND (power), H17 GND (power), J9 GND (power), J10 GND (power), J11 GND (power), J12 GND (power), K1 NC, K4 VCC (power), K9 GND (power), K10 GND (power), K11 GND (power), K12 GND (power), K17 NC, K18 NC, L9 GND (power), L10 GND (power), L11 GND (power), L12 GND (power), L17 VCC (power), M9 GND (power), M10 GND (power), M11 GND (power), M12 GND (power), N4 GND (power), N17 GND (power), P20 NC, R2 NC, R3 NC, R4 VCC (power), R17 VCC (power), R20 NC, U4 GND (power), U6 VCC (power), U8 GND (power), U10 VCC (power), U11 NC, U13 GND (power), U15 VCC (power), U17 GND (power), U19 NC, V5 NC, V7 NC, V11 NC, V14 NC, V18 NC, V19 NC, W2 NC, W3 NC, W7 NC, W11 NC, W15 NC, W17 NC, W19 NC, W20 NC, Y1 NC, Y2 NC, Y4 NC, Y10 NC, Y11 NC, Y18 NC, Y20 NC

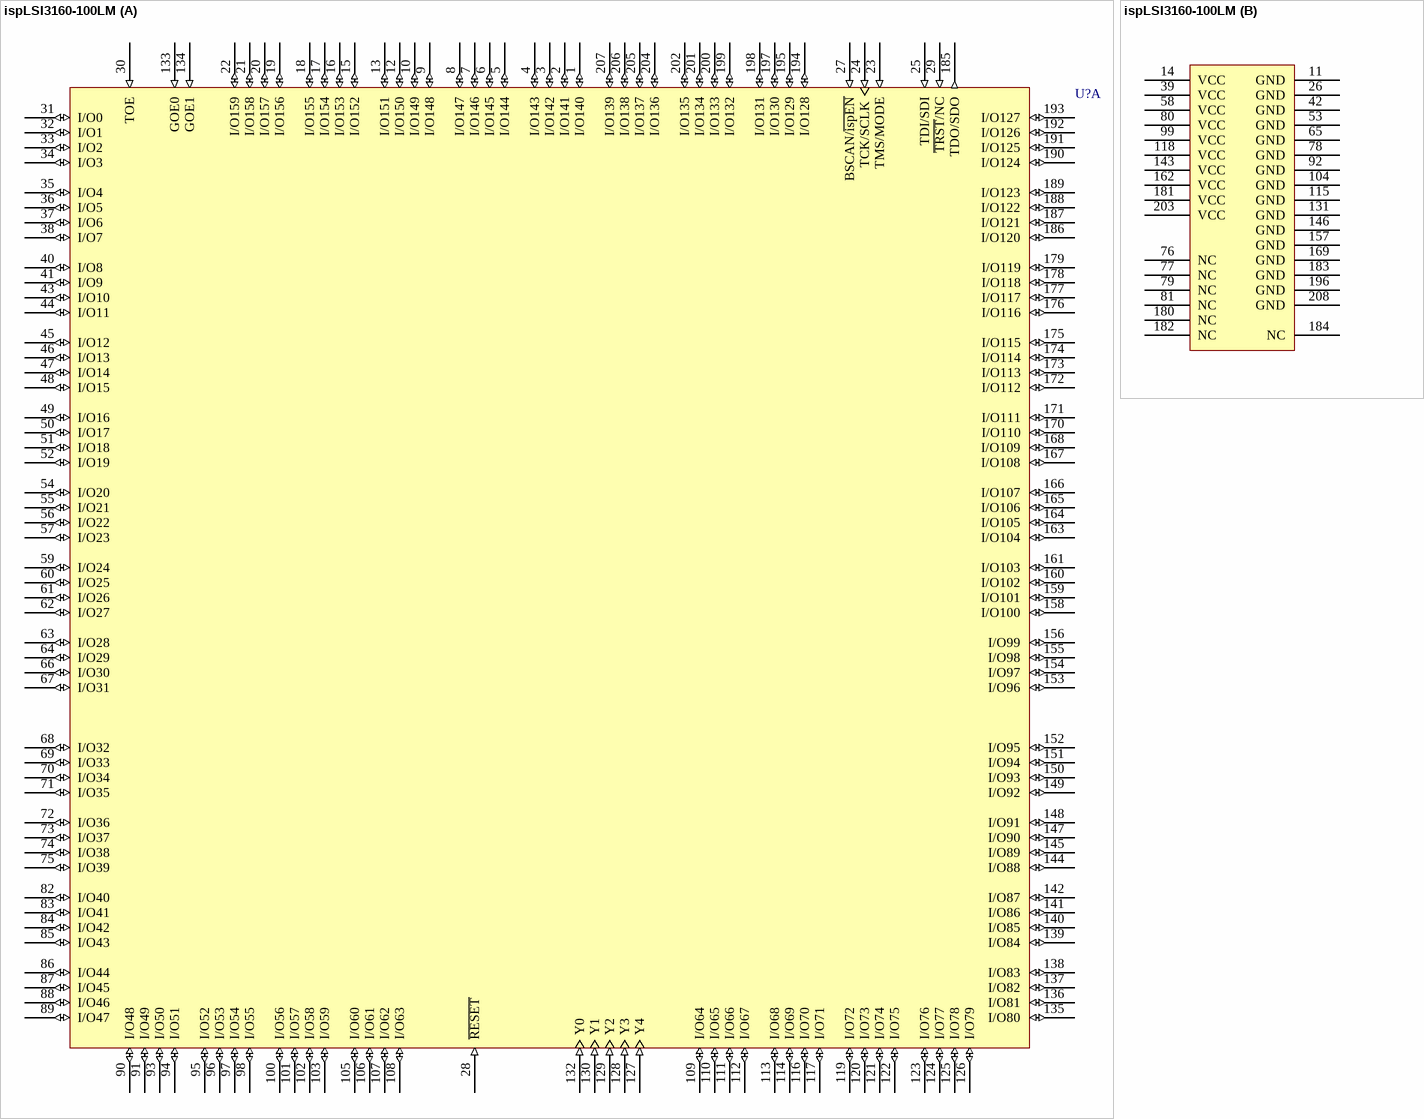
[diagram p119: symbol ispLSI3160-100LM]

## ispLSI3160-100LM
designator U?
In-System Programmable High-Density PLD
footprint MQFP208_N (Shrink QFP, 208-Leads, Body 27.7x27.7mm, Pitch 0.5mm, IPC Medium Density)
footprint MQFP208_L (Shrink QFP, 208-Leads, Body 27.7x27.7mm, Pitch 0.5mm, IPC High Density)
footprint MQFP208_M (Shrink QFP, 208-Leads, Body 27.7x27.7mm, Pitch 0.5mm, IPC Low Density)
3D model 3160-MQFP208 (208-Pin Shrink Quad Flat Pack 0.5 mm Pitch)
part A pins: 1 I/O140 (io), 2 I/O141 (io), 3 I/O142 (io), 4 I/O143 (io), 5 I/O144 (io), 6 I/O145 (io), 7 I/O146 (io), 8 I/O147 (io), 9 I/O148 (io), 10 I/O149 (io), 12 I/O150 (io), 13 I/O151 (io), 15 I/O152 (io), 16 I/O153 (io), 17 I/O154 (io), 18 I/O155 (io), 19 I/O156 (io), 20 I/O157 (io), 21 I/O158 (io), 22 I/O159 (io), 23 TMS/MODE (in), 24 TCK/SCLK (in), 25 TDI/SDI (in), 27 BSCAN/~{ispEN} (in), 28 ~{RESET} (in), 29 ~{TRST}/NC (in), 30 TOE (in), 31 I/O0 (io), 32 I/O1 (io), 33 I/O2 (io), 34 I/O3 (io), 35 I/O4 (io), 36 I/O5 (io), 37 I/O6 (io), 38 I/O7 (io), 40 I/O8 (io), 41 I/O9 (io), 43 I/O10 (io), 44 I/O11 (io), 45 I/O12 (io), 46 I/O13 (io), 47 I/O14 (io), 48 I/O15 (io), 49 I/O16 (io), 50 I/O17 (io), 51 I/O18 (io), 52 I/O19 (io), 54 I/O20 (io), 55 I/O21 (io), 56 I/O22 (io), 57 I/O23 (io), 59 I/O24 (io), 60 I/O25 (io), 61 I/O26 (io), 62 I/O27 (io), 63 I/O28 (io), 64 I/O29 (io), 66 I/O30 (io), 67 I/O31 (io), 68 I/O32 (io), 69 I/O33 (io), 70 I/O34 (io), 71 I/O35 (io), 72 I/O36 (io), 73 I/O37 (io), 74 I/O38 (io), 75 I/O39 (io), 82 I/O40 (io), 83 I/O41 (io), 84 I/O42 (io), 85 I/O43 (io), 86 I/O44 (io), 87 I/O45 (io), 88 I/O46 (io), 89 I/O47 (io), 90 I/O48 (io), 91 I/O49 (io), 93 I/O50 (io), 94 I/O51 (io), 95 I/O52 (io), 96 I/O53 (io), 97 I/O54 (io), 98 I/O55 (io), 100 I/O56 (io), 101 I/O57 (io), 102 I/O58 (io), 103 I/O59 (io), 105 I/O60 (io), 106 I/O61 (io), 107 I/O62 (io), 108 I/O63 (io), 109 I/O64 (io), 110 I/O65 (io), 111 I/O66 (io), 112 I/O67 (io), 113 I/O68 (io), 114 I/O69 (io), 116 I/O70 (io), 117 I/O71 (io), 119 I/O72 (io), 120 I/O73 (io), 121 I/O74 (io), 122 I/O75 (io), 123 I/O76 (io), 124 I/O77 (io), 125 I/O78 (io), 126 I/O79 (io), 127 Y4 (in), 128 Y3 (in), 129 Y2 (in), 130 Y1 (in), 132 Y0 (in), 133 GOE0 (in), 134 GOE1 (in), 135 I/O80 (io), 136 I/O81 (io), 137 I/O82 (io), 138 I/O83 (io), 139 I/O84 (io), 140 I/O85 (io), 141 I/O86 (io), 142 I/O87 (io), 144 I/O88 (io), 145 I/O89 (io), 147 I/O90 (io), 148 I/O91 (io), 149 I/O92 (io), 150 I/O93 (io), 151 I/O94 (io), 152 I/O95 (io), 153 I/O96 (io), 154 I/O97 (io), 155 I/O98 (io), 156 I/O99 (io), 158 I/O100 (io), 159 I/O101 (io), 160 I/O102 (io), 161 I/O103 (io), 163 I/O104 (io), 164 I/O105 (io), 165 I/O106 (io), 166 I/O107 (io), 167 I/O108 (io), 168 I/O109 (io), 170 I/O110 (io), 171 I/O111 (io), 172 I/O112 (io), 173 I/O113 (io), 174 I/O114 (io), 175 I/O115 (io), 176 I/O116 (io), 177 I/O117 (io), 178 I/O118 (io), 179 I/O119 (io), 185 TDO/SDO (out), 186 I/O120 (io), 187 I/O121 (io), 188 I/O122 (io), 189 I/O123 (io), 190 I/O124 (io), 191 I/O125 (io), 192 I/O126 (io), 193 I/O127 (io), 194 I/O128 (io), 195 I/O129 (io), 197 I/O130 (io), 198 I/O131 (io), 199 I/O132 (io), 200 I/O133 (io), 201 I/O134 (io), 202 I/O135 (io), 204 I/O136 (io), 205 I/O137 (io), 206 I/O138 (io), 207 I/O139 (io)
part B pins: 11 GND (power), 14 VCC (power), 26 GND (power), 39 VCC (power), 42 GND (power), 53 GND (power), 58 VCC (power), 65 GND (power), 76 NC, 77 NC, 78 GND (power), 79 NC, 80 VCC (power), 81 NC, 92 GND (power), 99 VCC (power), 104 GND (power), 115 GND (power), 118 VCC (power), 131 GND (power), 143 VCC (power), 146 GND (power), 157 GND (power), 162 VCC (power), 169 GND (power), 180 NC, 181 VCC (power), 182 NC, 183 GND (power), 184 NC, 196 GND (power), 203 VCC (power), 208 GND (power)

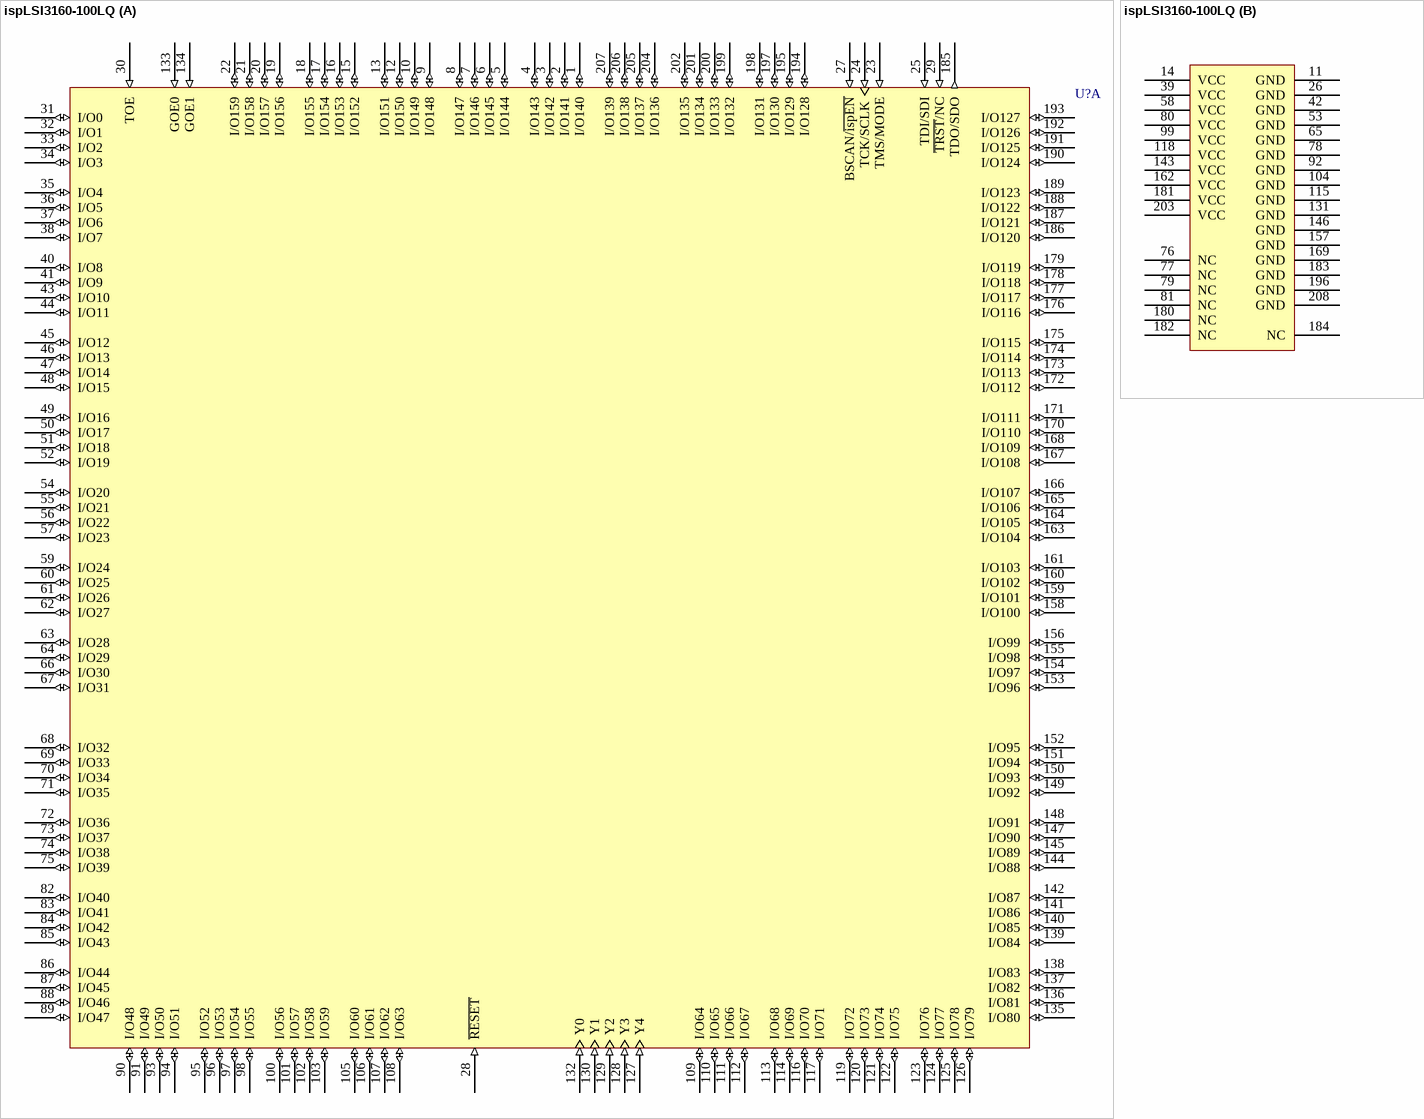
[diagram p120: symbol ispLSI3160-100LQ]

## ispLSI3160-100LQ
designator U?
In-System Programmable High-Density PLD
footprint PQFP208_N (Shrink QFP, 208-Leads, Body 28x28mm, Pitch 0.5mm, IPC Medium Density)
footprint PQFP208_L (Shrink QFP, 208-Leads, Body 28x28mm, Pitch 0.5mm, IPC High Density)
footprint PQFP208_M (Shrink QFP, 208-Leads, Body 28x28mm, Pitch 0.5mm, IPC Low Density)
3D model 3160-PQFP208 (208-Pin Plastic Quad Flat Pack (PQFP208))
part A pins: 1 I/O140 (io), 2 I/O141 (io), 3 I/O142 (io), 4 I/O143 (io), 5 I/O144 (io), 6 I/O145 (io), 7 I/O146 (io), 8 I/O147 (io), 9 I/O148 (io), 10 I/O149 (io), 12 I/O150 (io), 13 I/O151 (io), 15 I/O152 (io), 16 I/O153 (io), 17 I/O154 (io), 18 I/O155 (io), 19 I/O156 (io), 20 I/O157 (io), 21 I/O158 (io), 22 I/O159 (io), 23 TMS/MODE (in), 24 TCK/SCLK (in), 25 TDI/SDI (in), 27 BSCAN/~{ispEN} (in), 28 ~{RESET} (in), 29 ~{TRST}/NC (in), 30 TOE (in), 31 I/O0 (io), 32 I/O1 (io), 33 I/O2 (io), 34 I/O3 (io), 35 I/O4 (io), 36 I/O5 (io), 37 I/O6 (io), 38 I/O7 (io), 40 I/O8 (io), 41 I/O9 (io), 43 I/O10 (io), 44 I/O11 (io), 45 I/O12 (io), 46 I/O13 (io), 47 I/O14 (io), 48 I/O15 (io), 49 I/O16 (io), 50 I/O17 (io), 51 I/O18 (io), 52 I/O19 (io), 54 I/O20 (io), 55 I/O21 (io), 56 I/O22 (io), 57 I/O23 (io), 59 I/O24 (io), 60 I/O25 (io), 61 I/O26 (io), 62 I/O27 (io), 63 I/O28 (io), 64 I/O29 (io), 66 I/O30 (io), 67 I/O31 (io), 68 I/O32 (io), 69 I/O33 (io), 70 I/O34 (io), 71 I/O35 (io), 72 I/O36 (io), 73 I/O37 (io), 74 I/O38 (io), 75 I/O39 (io), 82 I/O40 (io), 83 I/O41 (io), 84 I/O42 (io), 85 I/O43 (io), 86 I/O44 (io), 87 I/O45 (io), 88 I/O46 (io), 89 I/O47 (io), 90 I/O48 (io), 91 I/O49 (io), 93 I/O50 (io), 94 I/O51 (io), 95 I/O52 (io), 96 I/O53 (io), 97 I/O54 (io), 98 I/O55 (io), 100 I/O56 (io), 101 I/O57 (io), 102 I/O58 (io), 103 I/O59 (io), 105 I/O60 (io), 106 I/O61 (io), 107 I/O62 (io), 108 I/O63 (io), 109 I/O64 (io), 110 I/O65 (io), 111 I/O66 (io), 112 I/O67 (io), 113 I/O68 (io), 114 I/O69 (io), 116 I/O70 (io), 117 I/O71 (io), 119 I/O72 (io), 120 I/O73 (io), 121 I/O74 (io), 122 I/O75 (io), 123 I/O76 (io), 124 I/O77 (io), 125 I/O78 (io), 126 I/O79 (io), 127 Y4 (in), 128 Y3 (in), 129 Y2 (in), 130 Y1 (in), 132 Y0 (in), 133 GOE0 (in), 134 GOE1 (in), 135 I/O80 (io), 136 I/O81 (io), 137 I/O82 (io), 138 I/O83 (io), 139 I/O84 (io), 140 I/O85 (io), 141 I/O86 (io), 142 I/O87 (io), 144 I/O88 (io), 145 I/O89 (io), 147 I/O90 (io), 148 I/O91 (io), 149 I/O92 (io), 150 I/O93 (io), 151 I/O94 (io), 152 I/O95 (io), 153 I/O96 (io), 154 I/O97 (io), 155 I/O98 (io), 156 I/O99 (io), 158 I/O100 (io), 159 I/O101 (io), 160 I/O102 (io), 161 I/O103 (io), 163 I/O104 (io), 164 I/O105 (io), 165 I/O106 (io), 166 I/O107 (io), 167 I/O108 (io), 168 I/O109 (io), 170 I/O110 (io), 171 I/O111 (io), 172 I/O112 (io), 173 I/O113 (io), 174 I/O114 (io), 175 I/O115 (io), 176 I/O116 (io), 177 I/O117 (io), 178 I/O118 (io), 179 I/O119 (io), 185 TDO/SDO (out), 186 I/O120 (io), 187 I/O121 (io), 188 I/O122 (io), 189 I/O123 (io), 190 I/O124 (io), 191 I/O125 (io), 192 I/O126 (io), 193 I/O127 (io), 194 I/O128 (io), 195 I/O129 (io), 197 I/O130 (io), 198 I/O131 (io), 199 I/O132 (io), 200 I/O133 (io), 201 I/O134 (io), 202 I/O135 (io), 204 I/O136 (io), 205 I/O137 (io), 206 I/O138 (io), 207 I/O139 (io)
part B pins: 11 GND (power), 14 VCC (power), 26 GND (power), 39 VCC (power), 42 GND (power), 53 GND (power), 58 VCC (power), 65 GND (power), 76 NC, 77 NC, 78 GND (power), 79 NC, 80 VCC (power), 81 NC, 92 GND (power), 99 VCC (power), 104 GND (power), 115 GND (power), 118 VCC (power), 131 GND (power), 143 VCC (power), 146 GND (power), 157 GND (power), 162 VCC (power), 169 GND (power), 180 NC, 181 VCC (power), 182 NC, 183 GND (power), 184 NC, 196 GND (power), 203 VCC (power), 208 GND (power)

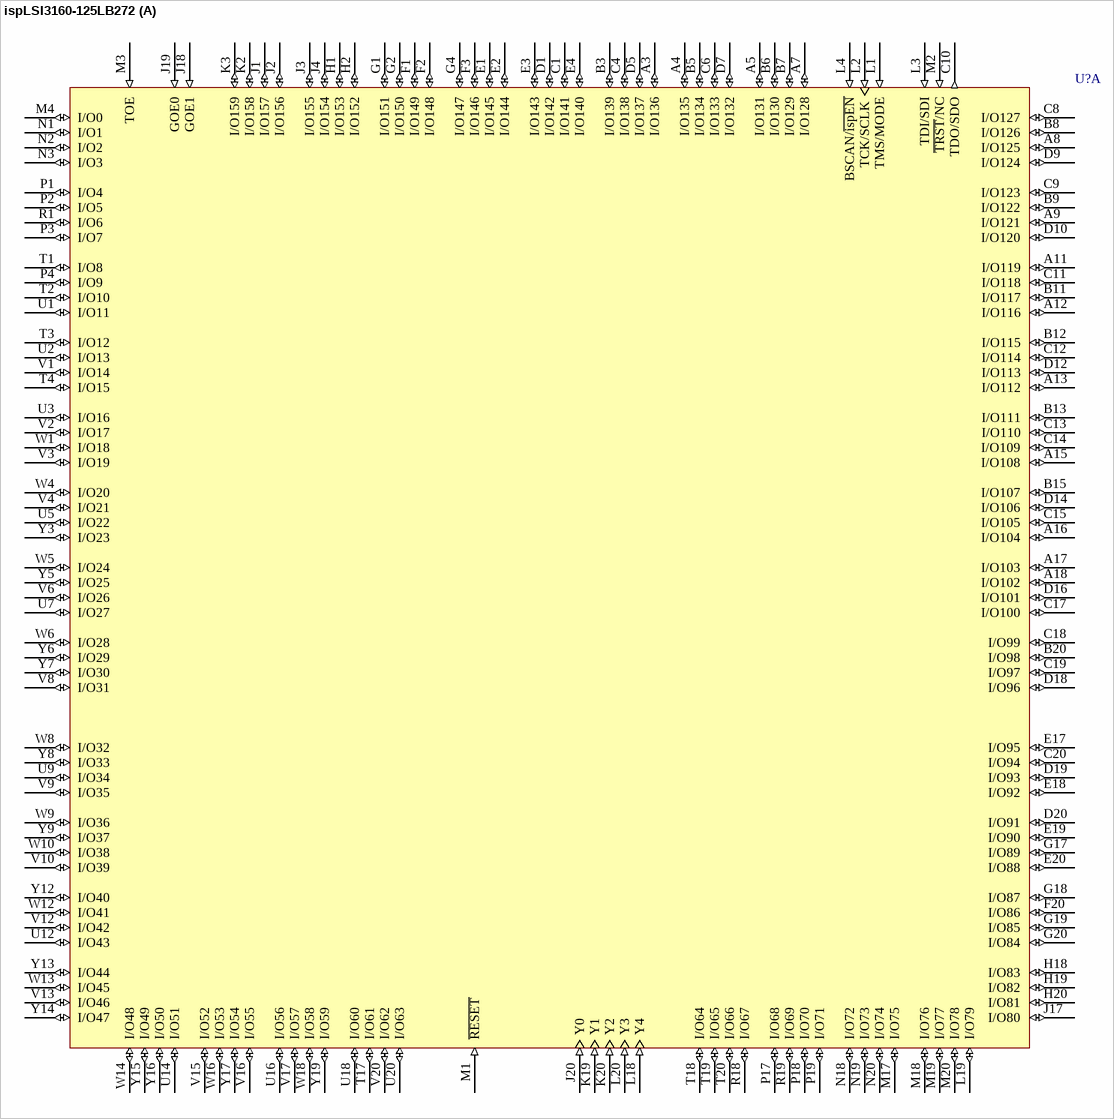
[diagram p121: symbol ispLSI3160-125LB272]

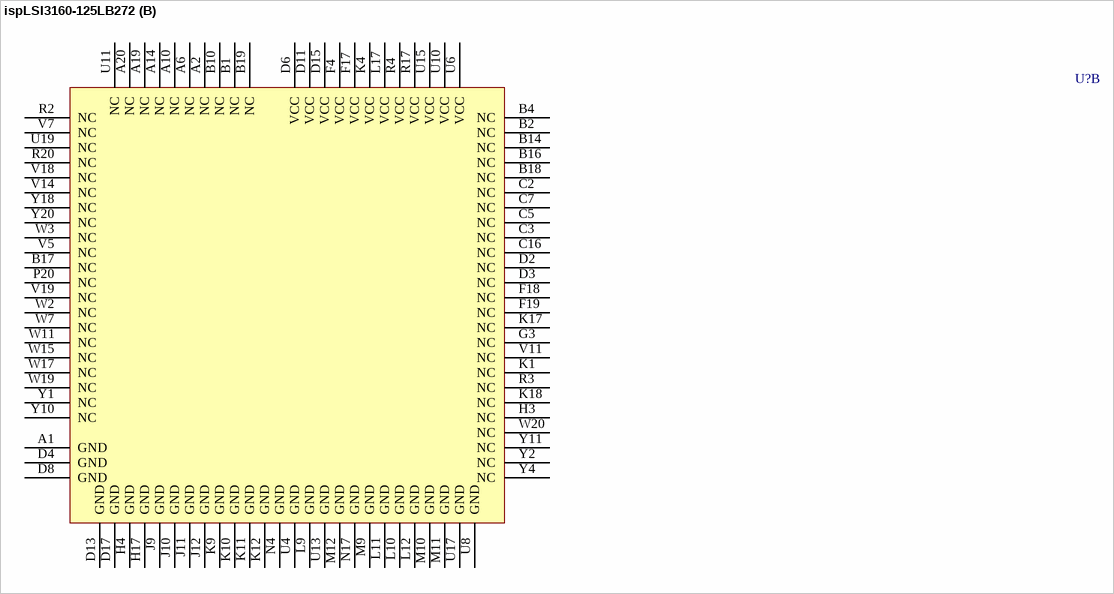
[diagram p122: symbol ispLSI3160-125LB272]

## ispLSI3160-125LB272
designator U?
In-System Programmable High-Density PLD
footprint BGA272 (BGA, 272-Leads, Body 27x27mm, Pitch 1.27mm)
3D model 3160-BGA272 (272-Ball Ball Grid Array (BGA272))
part A pins: A3 I/O136 (io), A4 I/O135 (io), A5 I/O131 (io), A7 I/O128 (io), A8 I/O125 (io), A9 I/O121 (io), A11 I/O119 (io), A12 I/O116 (io), A13 I/O112 (io), A15 I/O108 (io), A16 I/O104 (io), A17 I/O103 (io), A18 I/O102 (io), B3 I/O139 (io), B5 I/O134 (io), B6 I/O130 (io), B7 I/O129 (io), B8 I/O126 (io), B9 I/O122 (io), B11 I/O117 (io), B12 I/O115 (io), B13 I/O111 (io), B15 I/O107 (io), B20 I/O98 (io), C1 I/O141 (io), C4 I/O138 (io), C6 I/O133 (io), C8 I/O127 (io), C9 I/O123 (io), C10 TDO/SDO (out), C11 I/O118 (io), C12 I/O114 (io), C13 I/O110 (io), C14 I/O109 (io), C15 I/O105 (io), C17 I/O100 (io), C18 I/O99 (io), C19 I/O97 (io), C20 I/O94 (io), D1 I/O142 (io), D5 I/O137 (io), D7 I/O132 (io), D9 I/O124 (io), D10 I/O120 (io), D12 I/O113 (io), D14 I/O106 (io), D16 I/O101 (io), D18 I/O96 (io), D19 I/O93 (io), D20 I/O91 (io), E1 I/O145 (io), E2 I/O144 (io), E3 I/O143 (io), E4 I/O140 (io), E17 I/O95 (io), E18 I/O92 (io), E19 I/O90 (io), E20 I/O88 (io), F1 I/O149 (io), F2 I/O148 (io), F3 I/O146 (io), F20 I/O86 (io), G1 I/O151 (io), G2 I/O150 (io), G4 I/O147 (io), G17 I/O89 (io), G18 I/O87 (io), G19 I/O85 (io), G20 I/O84 (io), H1 I/O153 (io), H2 I/O152 (io), H18 I/O83 (io), H19 I/O82 (io), H20 I/O81 (io), J1 I/O157 (io), J2 I/O156 (io), J3 I/O155 (io), J4 I/O154 (io), J17 I/O80 (io), J18 GOE1 (in), J19 GOE0 (in), J20 Y0 (in), K2 I/O158 (io), K3 I/O159 (io), K19 Y1 (in), K20 Y2 (in), L1 TMS/MODE (in), L2 TCK/SCLK (in), L3 TDI/SDI (in), L4 BSCAN/~{ispEN} (in), L18 Y4 (in), L19 I/O79 (io), L20 Y3 (in), M1 ~{RESET} (in), M2 ~{TRST}/NC (in), M3 TOE (in), M4 I/O0 (io), M17 I/O75 (io), M18 I/O76 (io), M19 I/O77 (io), M20 I/O78 (io), N1 I/O1 (io), N2 I/O2 (io), N3 I/O3 (io), N18 I/O72 (io), N19 I/O73 (io), N20 I/O74 (io), P1 I/O4 (io), P2 I/O5 (io), P3 I/O7 (io), P4 I/O9 (io), P17 I/O68 (io), P18 I/O70 (io), P19 I/O71 (io), R1 I/O6 (io), R18 I/O67 (io), R19 I/O69 (io), T1 I/O8 (io), T2 I/O10 (io), T3 I/O12 (io), T4 I/O15 (io), T17 I/O61 (io), T18 I/O64 (io), T19 I/O65 (io), T20 I/O66 (io), U1 I/O11 (io), U2 I/O13 (io), U3 I/O16 (io), U5 I/O22 (io), U7 I/O27 (io), U9 I/O34 (io), U12 I/O43 (io), U14 I/O51 (io), U16 I/O56 (io), U18 I/O60 (io), U20 I/O63 (io), V1 I/O14 (io), V2 I/O17 (io), V3 I/O19 (io), V4 I/O21 (io), V6 I/O26 (io), V8 I/O31 (io), V9 I/O35 (io), V10 I/O39 (io), V12 I/O42 (io), V13 I/O46 (io), V15 I/O52 (io), V16 I/O55 (io), V17 I/O57 (io), V20 I/O62 (io), W1 I/O18 (io), W4 I/O20 (io), W5 I/O24 (io), W6 I/O28 (io), W8 I/O32 (io), W9 I/O36 (io), W10 I/O38 (io), W12 I/O41 (io), W13 I/O45 (io), W14 I/O48 (io), W16 I/O53 (io), W18 I/O58 (io), Y3 I/O23 (io), Y5 I/O25 (io), Y6 I/O29 (io), Y7 I/O30 (io), Y8 I/O33 (io), Y9 I/O37 (io), Y12 I/O40 (io), Y13 I/O44 (io), Y14 I/O47 (io), Y15 I/O49 (io), Y16 I/O50 (io), Y17 I/O54 (io), Y19 I/O59 (io)
part B pins: A1 GND (power), A2 NC, A6 NC, A10 NC, A14 NC, A19 NC, A20 NC, B1 NC, B2 NC, B4 NC, B10 NC, B14 NC, B16 NC, B17 NC, B18 NC, B19 NC, C2 NC, C3 NC, C5 NC, C7 NC, C16 NC, D2 NC, D3 NC, D4 GND (power), D6 VCC (power), D8 GND (power), D11 VCC (power), D13 GND (power), D15 VCC (power), D17 GND (power), F4 VCC (power), F17 VCC (power), F18 NC, F19 NC, G3 NC, H3 NC, H4 GND (power), H17 GND (power), J9 GND (power), J10 GND (power), J11 GND (power), J12 GND (power), K1 NC, K4 VCC (power), K9 GND (power), K10 GND (power), K11 GND (power), K12 GND (power), K17 NC, K18 NC, L9 GND (power), L10 GND (power), L11 GND (power), L12 GND (power), L17 VCC (power), M9 GND (power), M10 GND (power), M11 GND (power), M12 GND (power), N4 GND (power), N17 GND (power), P20 NC, R2 NC, R3 NC, R4 VCC (power), R17 VCC (power), R20 NC, U4 GND (power), U6 VCC (power), U8 GND (power), U10 VCC (power), U11 NC, U13 GND (power), U15 VCC (power), U17 GND (power), U19 NC, V5 NC, V7 NC, V11 NC, V14 NC, V18 NC, V19 NC, W2 NC, W3 NC, W7 NC, W11 NC, W15 NC, W17 NC, W19 NC, W20 NC, Y1 NC, Y2 NC, Y4 NC, Y10 NC, Y11 NC, Y18 NC, Y20 NC

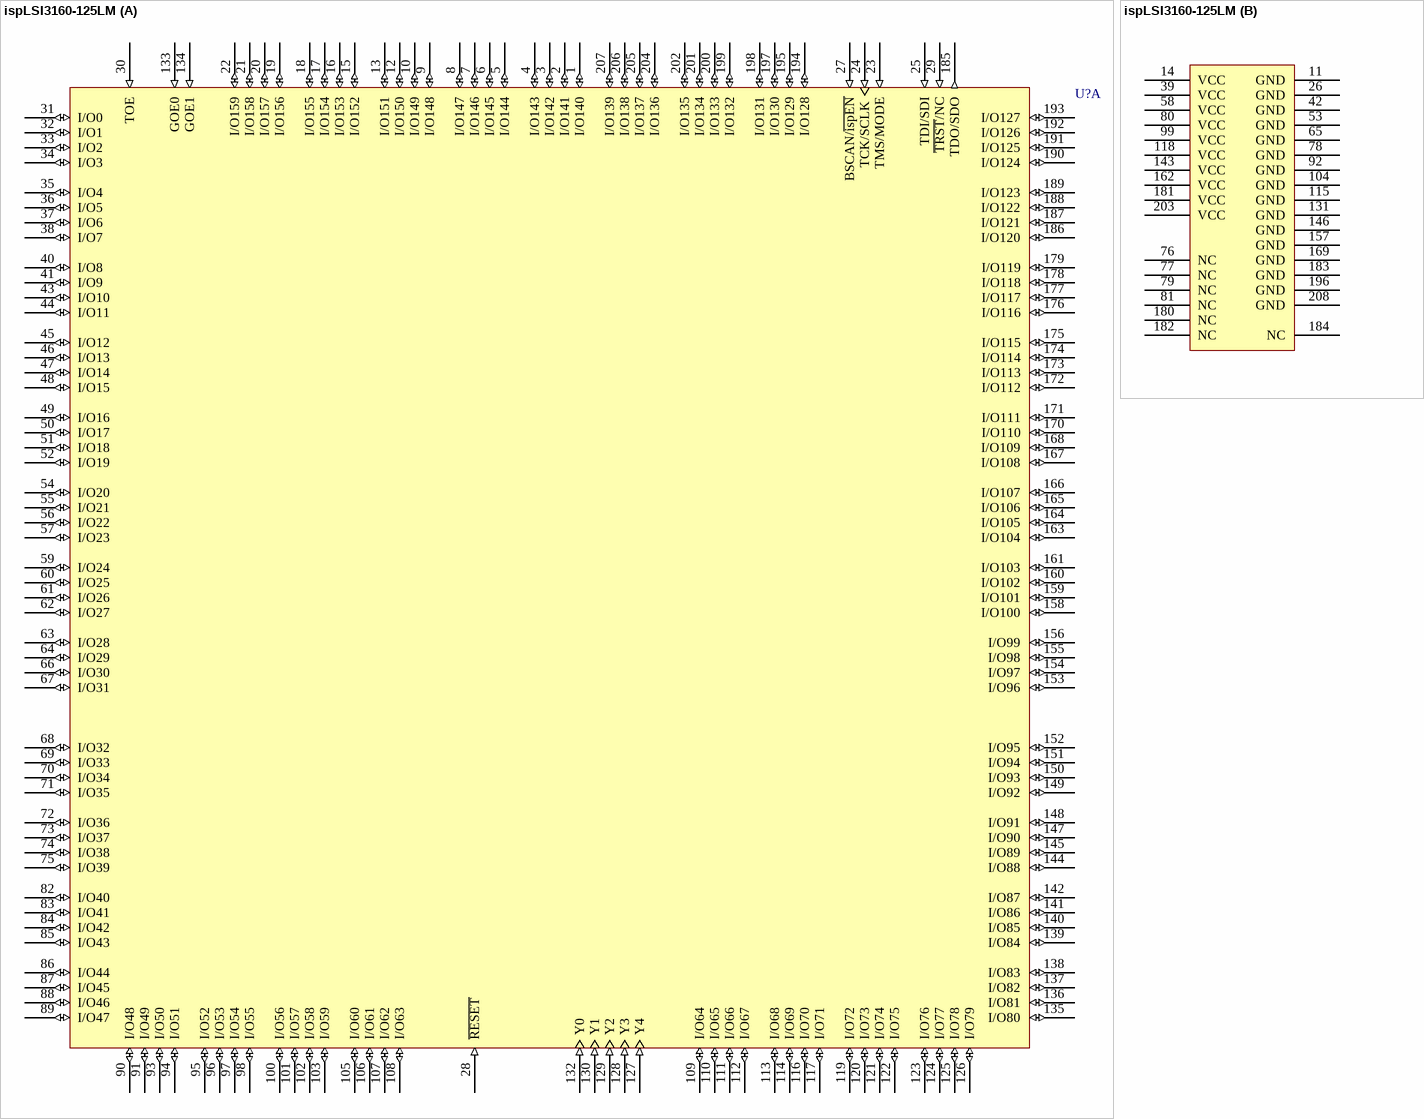
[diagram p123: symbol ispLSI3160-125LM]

## ispLSI3160-125LM
designator U?
In-System Programmable High-Density PLD
footprint MQFP208_N (Shrink QFP, 208-Leads, Body 27.7x27.7mm, Pitch 0.5mm, IPC Medium Density)
footprint MQFP208_L (Shrink QFP, 208-Leads, Body 27.7x27.7mm, Pitch 0.5mm, IPC High Density)
footprint MQFP208_M (Shrink QFP, 208-Leads, Body 27.7x27.7mm, Pitch 0.5mm, IPC Low Density)
3D model 3160-MQFP208 (208-Pin Shrink Quad Flat Pack 0.5 mm Pitch)
part A pins: 1 I/O140 (io), 2 I/O141 (io), 3 I/O142 (io), 4 I/O143 (io), 5 I/O144 (io), 6 I/O145 (io), 7 I/O146 (io), 8 I/O147 (io), 9 I/O148 (io), 10 I/O149 (io), 12 I/O150 (io), 13 I/O151 (io), 15 I/O152 (io), 16 I/O153 (io), 17 I/O154 (io), 18 I/O155 (io), 19 I/O156 (io), 20 I/O157 (io), 21 I/O158 (io), 22 I/O159 (io), 23 TMS/MODE (in), 24 TCK/SCLK (in), 25 TDI/SDI (in), 27 BSCAN/~{ispEN} (in), 28 ~{RESET} (in), 29 ~{TRST}/NC (in), 30 TOE (in), 31 I/O0 (io), 32 I/O1 (io), 33 I/O2 (io), 34 I/O3 (io), 35 I/O4 (io), 36 I/O5 (io), 37 I/O6 (io), 38 I/O7 (io), 40 I/O8 (io), 41 I/O9 (io), 43 I/O10 (io), 44 I/O11 (io), 45 I/O12 (io), 46 I/O13 (io), 47 I/O14 (io), 48 I/O15 (io), 49 I/O16 (io), 50 I/O17 (io), 51 I/O18 (io), 52 I/O19 (io), 54 I/O20 (io), 55 I/O21 (io), 56 I/O22 (io), 57 I/O23 (io), 59 I/O24 (io), 60 I/O25 (io), 61 I/O26 (io), 62 I/O27 (io), 63 I/O28 (io), 64 I/O29 (io), 66 I/O30 (io), 67 I/O31 (io), 68 I/O32 (io), 69 I/O33 (io), 70 I/O34 (io), 71 I/O35 (io), 72 I/O36 (io), 73 I/O37 (io), 74 I/O38 (io), 75 I/O39 (io), 82 I/O40 (io), 83 I/O41 (io), 84 I/O42 (io), 85 I/O43 (io), 86 I/O44 (io), 87 I/O45 (io), 88 I/O46 (io), 89 I/O47 (io), 90 I/O48 (io), 91 I/O49 (io), 93 I/O50 (io), 94 I/O51 (io), 95 I/O52 (io), 96 I/O53 (io), 97 I/O54 (io), 98 I/O55 (io), 100 I/O56 (io), 101 I/O57 (io), 102 I/O58 (io), 103 I/O59 (io), 105 I/O60 (io), 106 I/O61 (io), 107 I/O62 (io), 108 I/O63 (io), 109 I/O64 (io), 110 I/O65 (io), 111 I/O66 (io), 112 I/O67 (io), 113 I/O68 (io), 114 I/O69 (io), 116 I/O70 (io), 117 I/O71 (io), 119 I/O72 (io), 120 I/O73 (io), 121 I/O74 (io), 122 I/O75 (io), 123 I/O76 (io), 124 I/O77 (io), 125 I/O78 (io), 126 I/O79 (io), 127 Y4 (in), 128 Y3 (in), 129 Y2 (in), 130 Y1 (in), 132 Y0 (in), 133 GOE0 (in), 134 GOE1 (in), 135 I/O80 (io), 136 I/O81 (io), 137 I/O82 (io), 138 I/O83 (io), 139 I/O84 (io), 140 I/O85 (io), 141 I/O86 (io), 142 I/O87 (io), 144 I/O88 (io), 145 I/O89 (io), 147 I/O90 (io), 148 I/O91 (io), 149 I/O92 (io), 150 I/O93 (io), 151 I/O94 (io), 152 I/O95 (io), 153 I/O96 (io), 154 I/O97 (io), 155 I/O98 (io), 156 I/O99 (io), 158 I/O100 (io), 159 I/O101 (io), 160 I/O102 (io), 161 I/O103 (io), 163 I/O104 (io), 164 I/O105 (io), 165 I/O106 (io), 166 I/O107 (io), 167 I/O108 (io), 168 I/O109 (io), 170 I/O110 (io), 171 I/O111 (io), 172 I/O112 (io), 173 I/O113 (io), 174 I/O114 (io), 175 I/O115 (io), 176 I/O116 (io), 177 I/O117 (io), 178 I/O118 (io), 179 I/O119 (io), 185 TDO/SDO (out), 186 I/O120 (io), 187 I/O121 (io), 188 I/O122 (io), 189 I/O123 (io), 190 I/O124 (io), 191 I/O125 (io), 192 I/O126 (io), 193 I/O127 (io), 194 I/O128 (io), 195 I/O129 (io), 197 I/O130 (io), 198 I/O131 (io), 199 I/O132 (io), 200 I/O133 (io), 201 I/O134 (io), 202 I/O135 (io), 204 I/O136 (io), 205 I/O137 (io), 206 I/O138 (io), 207 I/O139 (io)
part B pins: 11 GND (power), 14 VCC (power), 26 GND (power), 39 VCC (power), 42 GND (power), 53 GND (power), 58 VCC (power), 65 GND (power), 76 NC, 77 NC, 78 GND (power), 79 NC, 80 VCC (power), 81 NC, 92 GND (power), 99 VCC (power), 104 GND (power), 115 GND (power), 118 VCC (power), 131 GND (power), 143 VCC (power), 146 GND (power), 157 GND (power), 162 VCC (power), 169 GND (power), 180 NC, 181 VCC (power), 182 NC, 183 GND (power), 184 NC, 196 GND (power), 203 VCC (power), 208 GND (power)

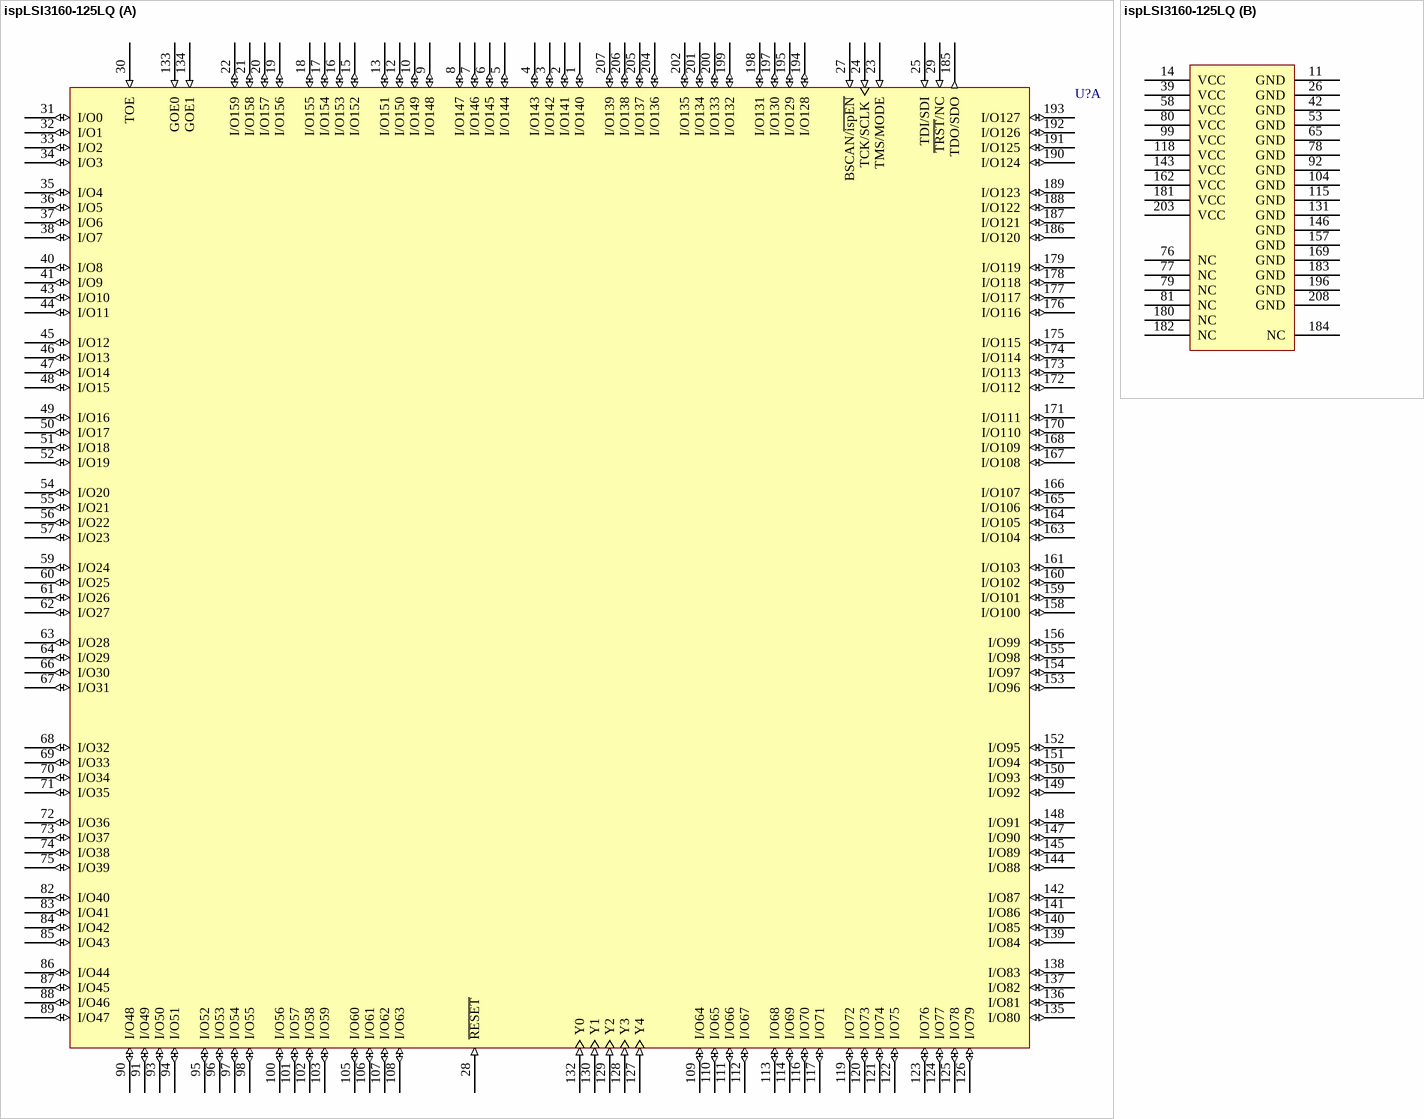
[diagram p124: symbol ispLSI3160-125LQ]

## ispLSI3160-125LQ
designator U?
In-System Programmable High-Density PLD
footprint PQFP208_N (Shrink QFP, 208-Leads, Body 28x28mm, Pitch 0.5mm, IPC Medium Density)
footprint PQFP208_L (Shrink QFP, 208-Leads, Body 28x28mm, Pitch 0.5mm, IPC High Density)
footprint PQFP208_M (Shrink QFP, 208-Leads, Body 28x28mm, Pitch 0.5mm, IPC Low Density)
3D model 3160-PQFP208 (208-Pin Plastic Quad Flat Pack (PQFP208))
part A pins: 1 I/O140 (io), 2 I/O141 (io), 3 I/O142 (io), 4 I/O143 (io), 5 I/O144 (io), 6 I/O145 (io), 7 I/O146 (io), 8 I/O147 (io), 9 I/O148 (io), 10 I/O149 (io), 12 I/O150 (io), 13 I/O151 (io), 15 I/O152 (io), 16 I/O153 (io), 17 I/O154 (io), 18 I/O155 (io), 19 I/O156 (io), 20 I/O157 (io), 21 I/O158 (io), 22 I/O159 (io), 23 TMS/MODE (in), 24 TCK/SCLK (in), 25 TDI/SDI (in), 27 BSCAN/~{ispEN} (in), 28 ~{RESET} (in), 29 ~{TRST}/NC (in), 30 TOE (in), 31 I/O0 (io), 32 I/O1 (io), 33 I/O2 (io), 34 I/O3 (io), 35 I/O4 (io), 36 I/O5 (io), 37 I/O6 (io), 38 I/O7 (io), 40 I/O8 (io), 41 I/O9 (io), 43 I/O10 (io), 44 I/O11 (io), 45 I/O12 (io), 46 I/O13 (io), 47 I/O14 (io), 48 I/O15 (io), 49 I/O16 (io), 50 I/O17 (io), 51 I/O18 (io), 52 I/O19 (io), 54 I/O20 (io), 55 I/O21 (io), 56 I/O22 (io), 57 I/O23 (io), 59 I/O24 (io), 60 I/O25 (io), 61 I/O26 (io), 62 I/O27 (io), 63 I/O28 (io), 64 I/O29 (io), 66 I/O30 (io), 67 I/O31 (io), 68 I/O32 (io), 69 I/O33 (io), 70 I/O34 (io), 71 I/O35 (io), 72 I/O36 (io), 73 I/O37 (io), 74 I/O38 (io), 75 I/O39 (io), 82 I/O40 (io), 83 I/O41 (io), 84 I/O42 (io), 85 I/O43 (io), 86 I/O44 (io), 87 I/O45 (io), 88 I/O46 (io), 89 I/O47 (io), 90 I/O48 (io), 91 I/O49 (io), 93 I/O50 (io), 94 I/O51 (io), 95 I/O52 (io), 96 I/O53 (io), 97 I/O54 (io), 98 I/O55 (io), 100 I/O56 (io), 101 I/O57 (io), 102 I/O58 (io), 103 I/O59 (io), 105 I/O60 (io), 106 I/O61 (io), 107 I/O62 (io), 108 I/O63 (io), 109 I/O64 (io), 110 I/O65 (io), 111 I/O66 (io), 112 I/O67 (io), 113 I/O68 (io), 114 I/O69 (io), 116 I/O70 (io), 117 I/O71 (io), 119 I/O72 (io), 120 I/O73 (io), 121 I/O74 (io), 122 I/O75 (io), 123 I/O76 (io), 124 I/O77 (io), 125 I/O78 (io), 126 I/O79 (io), 127 Y4 (in), 128 Y3 (in), 129 Y2 (in), 130 Y1 (in), 132 Y0 (in), 133 GOE0 (in), 134 GOE1 (in), 135 I/O80 (io), 136 I/O81 (io), 137 I/O82 (io), 138 I/O83 (io), 139 I/O84 (io), 140 I/O85 (io), 141 I/O86 (io), 142 I/O87 (io), 144 I/O88 (io), 145 I/O89 (io), 147 I/O90 (io), 148 I/O91 (io), 149 I/O92 (io), 150 I/O93 (io), 151 I/O94 (io), 152 I/O95 (io), 153 I/O96 (io), 154 I/O97 (io), 155 I/O98 (io), 156 I/O99 (io), 158 I/O100 (io), 159 I/O101 (io), 160 I/O102 (io), 161 I/O103 (io), 163 I/O104 (io), 164 I/O105 (io), 165 I/O106 (io), 166 I/O107 (io), 167 I/O108 (io), 168 I/O109 (io), 170 I/O110 (io), 171 I/O111 (io), 172 I/O112 (io), 173 I/O113 (io), 174 I/O114 (io), 175 I/O115 (io), 176 I/O116 (io), 177 I/O117 (io), 178 I/O118 (io), 179 I/O119 (io), 185 TDO/SDO (out), 186 I/O120 (io), 187 I/O121 (io), 188 I/O122 (io), 189 I/O123 (io), 190 I/O124 (io), 191 I/O125 (io), 192 I/O126 (io), 193 I/O127 (io), 194 I/O128 (io), 195 I/O129 (io), 197 I/O130 (io), 198 I/O131 (io), 199 I/O132 (io), 200 I/O133 (io), 201 I/O134 (io), 202 I/O135 (io), 204 I/O136 (io), 205 I/O137 (io), 206 I/O138 (io), 207 I/O139 (io)
part B pins: 11 GND (power), 14 VCC (power), 26 GND (power), 39 VCC (power), 42 GND (power), 53 GND (power), 58 VCC (power), 65 GND (power), 76 NC, 77 NC, 78 GND (power), 79 NC, 80 VCC (power), 81 NC, 92 GND (power), 99 VCC (power), 104 GND (power), 115 GND (power), 118 VCC (power), 131 GND (power), 143 VCC (power), 146 GND (power), 157 GND (power), 162 VCC (power), 169 GND (power), 180 NC, 181 VCC (power), 182 NC, 183 GND (power), 184 NC, 196 GND (power), 203 VCC (power), 208 GND (power)

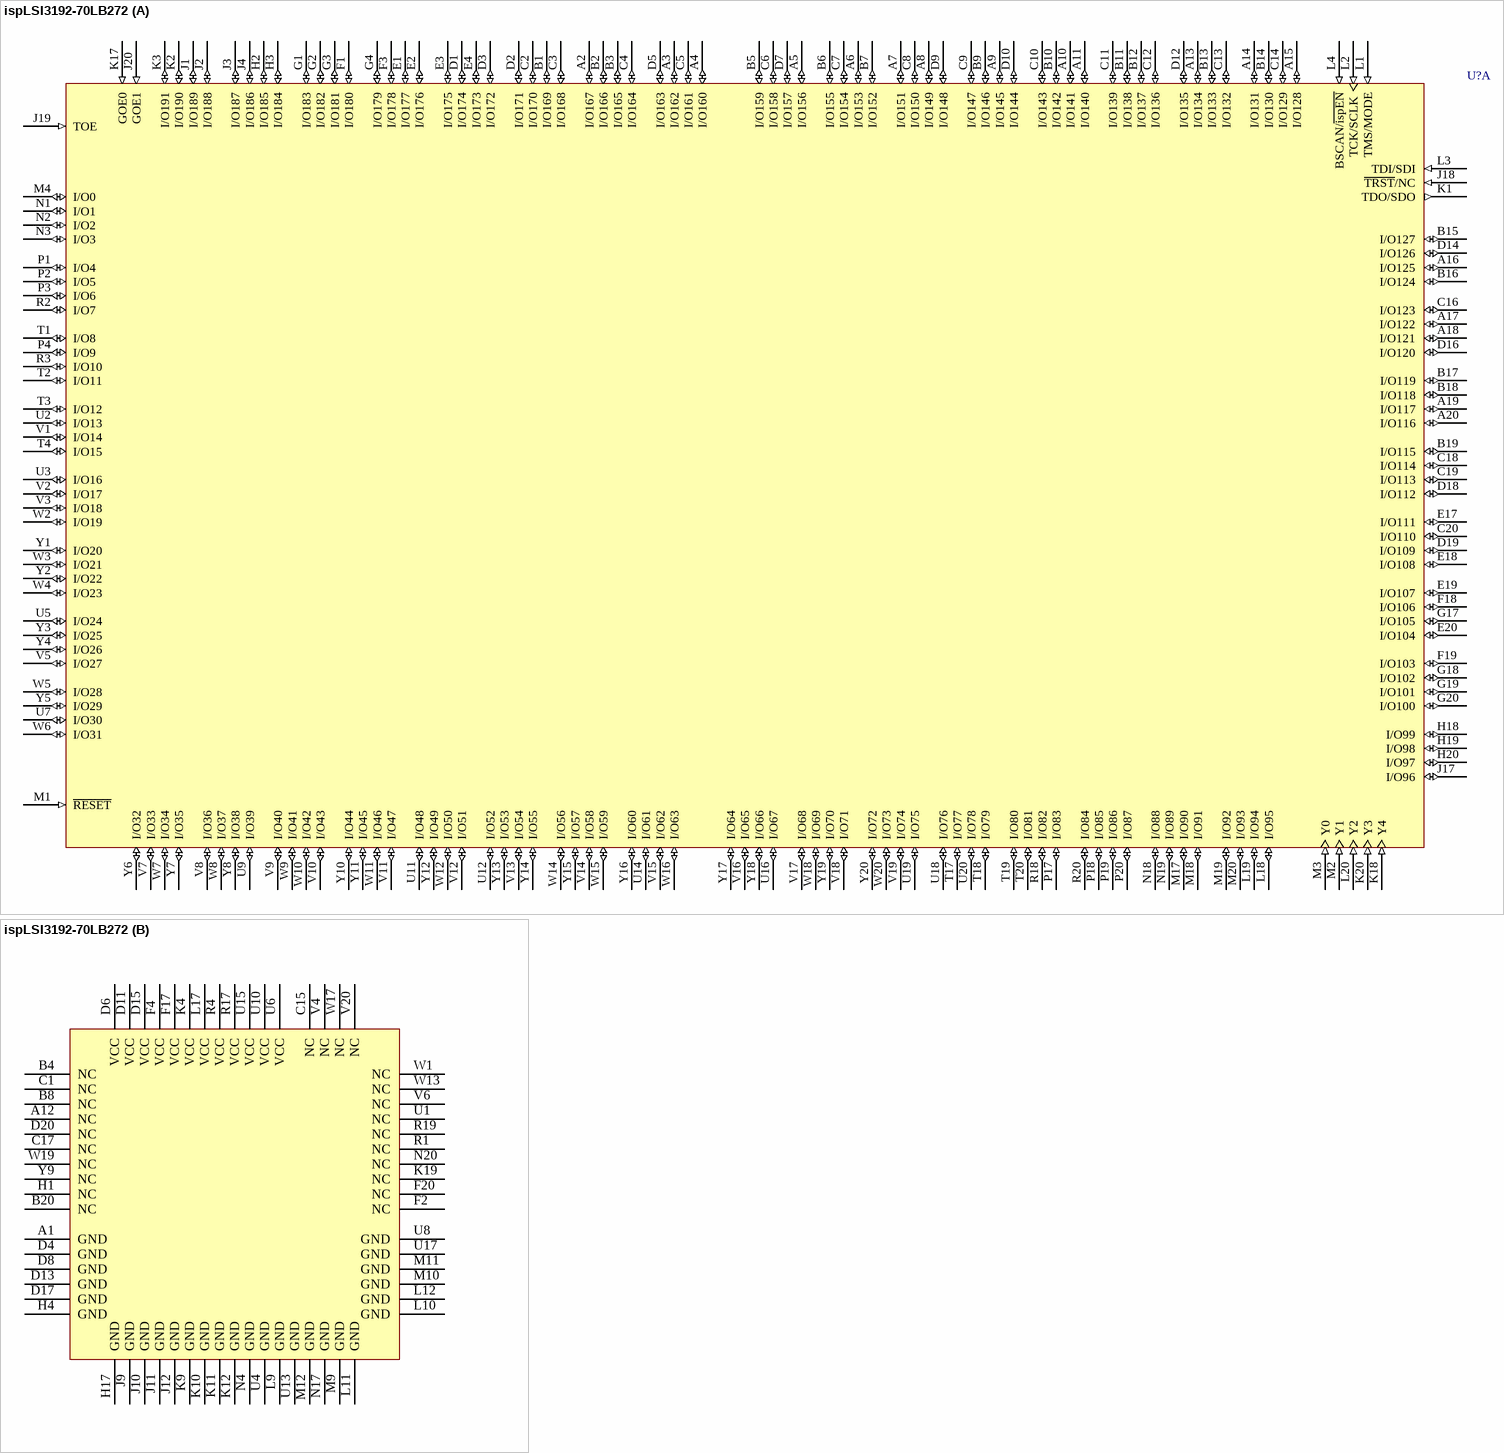
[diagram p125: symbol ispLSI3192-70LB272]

## ispLSI3192-70LB272
designator U?
High-Density Programmable Logic; Note: Pins J18, K1, L1, L2, L3 and L4 have dual function capability.
footprint BGA272 (BGA, 272-Leads, Body 27x27mm, Pitch 1.27mm)
3D model 3192-BGA272 (272-Ball Ball Grid Array (BGA272))
part A pins: A2 I/O167 (io), A3 I/O162 (io), A4 I/O160 (io), A5 I/O156 (io), A6 I/O153 (io), A7 I/O151 (io), A8 I/O149 (io), A9 I/O145 (io), A10 I/O141 (io), A11 I/O140 (io), A13 I/O134 (io), A14 I/O131 (io), A15 I/O128 (io), A16 I/O125 (io), A17 I/O122 (io), A18 I/O121 (io), A19 I/O117 (io), A20 I/O116 (io), B1 I/O169 (io), B2 I/O166 (io), B3 I/O165 (io), B5 I/O159 (io), B6 I/O155 (io), B7 I/O152 (io), B9 I/O146 (io), B10 I/O142 (io), B11 I/O138 (io), B12 I/O137 (io), B13 I/O133 (io), B14 I/O130 (io), B15 I/O127 (io), B16 I/O124 (io), B17 I/O119 (io), B18 I/O118 (io), B19 I/O115 (io), C2 I/O170 (io), C3 I/O168 (io), C4 I/O164 (io), C5 I/O161 (io), C6 I/O158 (io), C7 I/O154 (io), C8 I/O150 (io), C9 I/O147 (io), C10 I/O143 (io), C11 I/O139 (io), C12 I/O136 (io), C13 I/O132 (io), C14 I/O129 (io), C16 I/O123 (io), C18 I/O114 (io), C19 I/O113 (io), C20 I/O110 (io), D1 I/O174 (io), D2 I/O171 (io), D3 I/O172 (io), D5 I/O163 (io), D7 I/O157 (io), D9 I/O148 (io), D10 I/O144 (io), D12 I/O135 (io), D14 I/O126 (io), D16 I/O120 (io), D18 I/O112 (io), D19 I/O109 (io), E1 I/O177 (io), E2 I/O176 (io), E3 I/O175 (io), E4 I/O173 (io), E17 I/O111 (io), E18 I/O108 (io), E19 I/O107 (io), E20 I/O104 (io), F1 I/O180 (io), F3 I/O178 (io), F18 I/O106 (io), F19 I/O103 (io), G1 I/O183 (io), G2 I/O182 (io), G3 I/O181 (io), G4 I/O179 (io), G17 I/O105 (io), G18 I/O102 (io), G19 I/O101 (io), G20 I/O100 (io), H2 I/O185 (io), H3 I/O184 (io), H18 I/O99 (io), H19 I/O98 (io), H20 I/O97 (io), J1 I/O189 (io), J2 I/O188 (io), J3 I/O187 (io), J4 I/O186 (io), J17 I/O96 (io), J18 ~{TRST}/NC (in), J19 TOE (in), J20 GOE1 (in), K1 TDO/SDO (out), K2 I/O190 (io), K3 I/O191 (io), K17 GOE0 (in), K18 Y4 (in), K20 Y3 (in), L1 TMS/MODE (in), L2 TCK/SCLK (in), L3 TDI/SDI (in), L4 BSCAN/~{ispEN} (in), L18 I/O95 (io), L19 I/O94 (io), L20 Y2 (in), M1 ~{RESET} (in), M2 Y1 (in), M3 Y0 (in), M4 I/O0 (io), M17 I/O90 (io), M18 I/O91 (io), M19 I/O92 (io), M20 I/O93 (io), N1 I/O1 (io), N2 I/O2 (io), N3 I/O3 (io), N18 I/O88 (io), N19 I/O89 (io), P1 I/O4 (io), P2 I/O5 (io), P3 I/O6 (io), P4 I/O9 (io), P17 I/O83 (io), P18 I/O85 (io), P19 I/O86 (io), P20 I/O87 (io), R2 I/O7 (io), R3 I/O10 (io), R18 I/O82 (io), R20 I/O84 (io), T1 I/O8 (io), T2 I/O11 (io), T3 I/O12 (io), T4 I/O15 (io), T17 I/O77 (io), T18 I/O79 (io), T19 I/O80 (io), T20 I/O81 (io), U2 I/O13 (io), U3 I/O16 (io), U5 I/O24 (io), U7 I/O30 (io), U9 I/O39 (io), U11 I/O48 (io), U12 I/O52 (io), U14 I/O61 (io), U16 I/O67 (io), U18 I/O76 (io), U19 I/O75 (io), U20 I/O78 (io), V1 I/O14 (io), V2 I/O17 (io), V3 I/O18 (io), V5 I/O27 (io), V7 I/O33 (io), V8 I/O36 (io), V9 I/O40 (io), V10 I/O43 (io), V11 I/O47 (io), V12 I/O51 (io), V13 I/O54 (io), V14 I/O58 (io), V15 I/O62 (io), V16 I/O65 (io), V17 I/O68 (io), V18 I/O71 (io), V19 I/O74 (io), W2 I/O19 (io), W3 I/O21 (io), W4 I/O23 (io), W5 I/O28 (io), W6 I/O31 (io), W7 I/O34 (io), W8 I/O37 (io), W9 I/O41 (io), W10 I/O42 (io), W11 I/O46 (io), W12 I/O50 (io), W14 I/O56 (io), W15 I/O59 (io), W16 I/O63 (io), W18 I/O69 (io), W20 I/O73 (io), Y1 I/O20 (io), Y2 I/O22 (io), Y3 I/O25 (io), Y4 I/O26 (io), Y5 I/O29 (io), Y6 I/O32 (io), Y7 I/O35 (io), Y8 I/O38 (io), Y10 I/O44 (io), Y11 I/O45 (io), Y12 I/O49 (io), Y13 I/O53 (io), Y14 I/O55 (io), Y15 I/O57 (io), Y16 I/O60 (io), Y17 I/O64 (io), Y18 I/O66 (io), Y19 I/O70 (io), Y20 I/O72 (io)
part B pins: A1 GND (power), A12 NC, B4 NC, B8 NC, B20 NC, C1 NC, C15 NC, C17 NC, D4 GND (power), D6 VCC (power), D8 GND (power), D11 VCC (power), D13 GND (power), D15 VCC (power), D17 GND (power), D20 NC, F2 NC, F4 VCC (power), F17 VCC (power), F20 NC, H1 NC, H4 GND (power), H17 GND (power), J9 GND (power), J10 GND (power), J11 GND (power), J12 GND (power), K4 VCC (power), K9 GND (power), K10 GND (power), K11 GND (power), K12 GND (power), K19 NC, L9 GND (power), L10 GND (power), L11 GND (power), L12 GND (power), L17 VCC (power), M9 GND (power), M10 GND (power), M11 GND (power), M12 GND (power), N4 GND (power), N17 GND (power), N20 NC, R1 NC, R4 VCC (power), R17 VCC (power), R19 NC, U1 NC, U4 GND (power), U6 VCC (power), U8 GND (power), U10 VCC (power), U13 GND (power), U15 VCC (power), U17 GND (power), V4 NC, V6 NC, V20 NC, W1 NC, W13 NC, W17 NC, W19 NC, Y9 NC

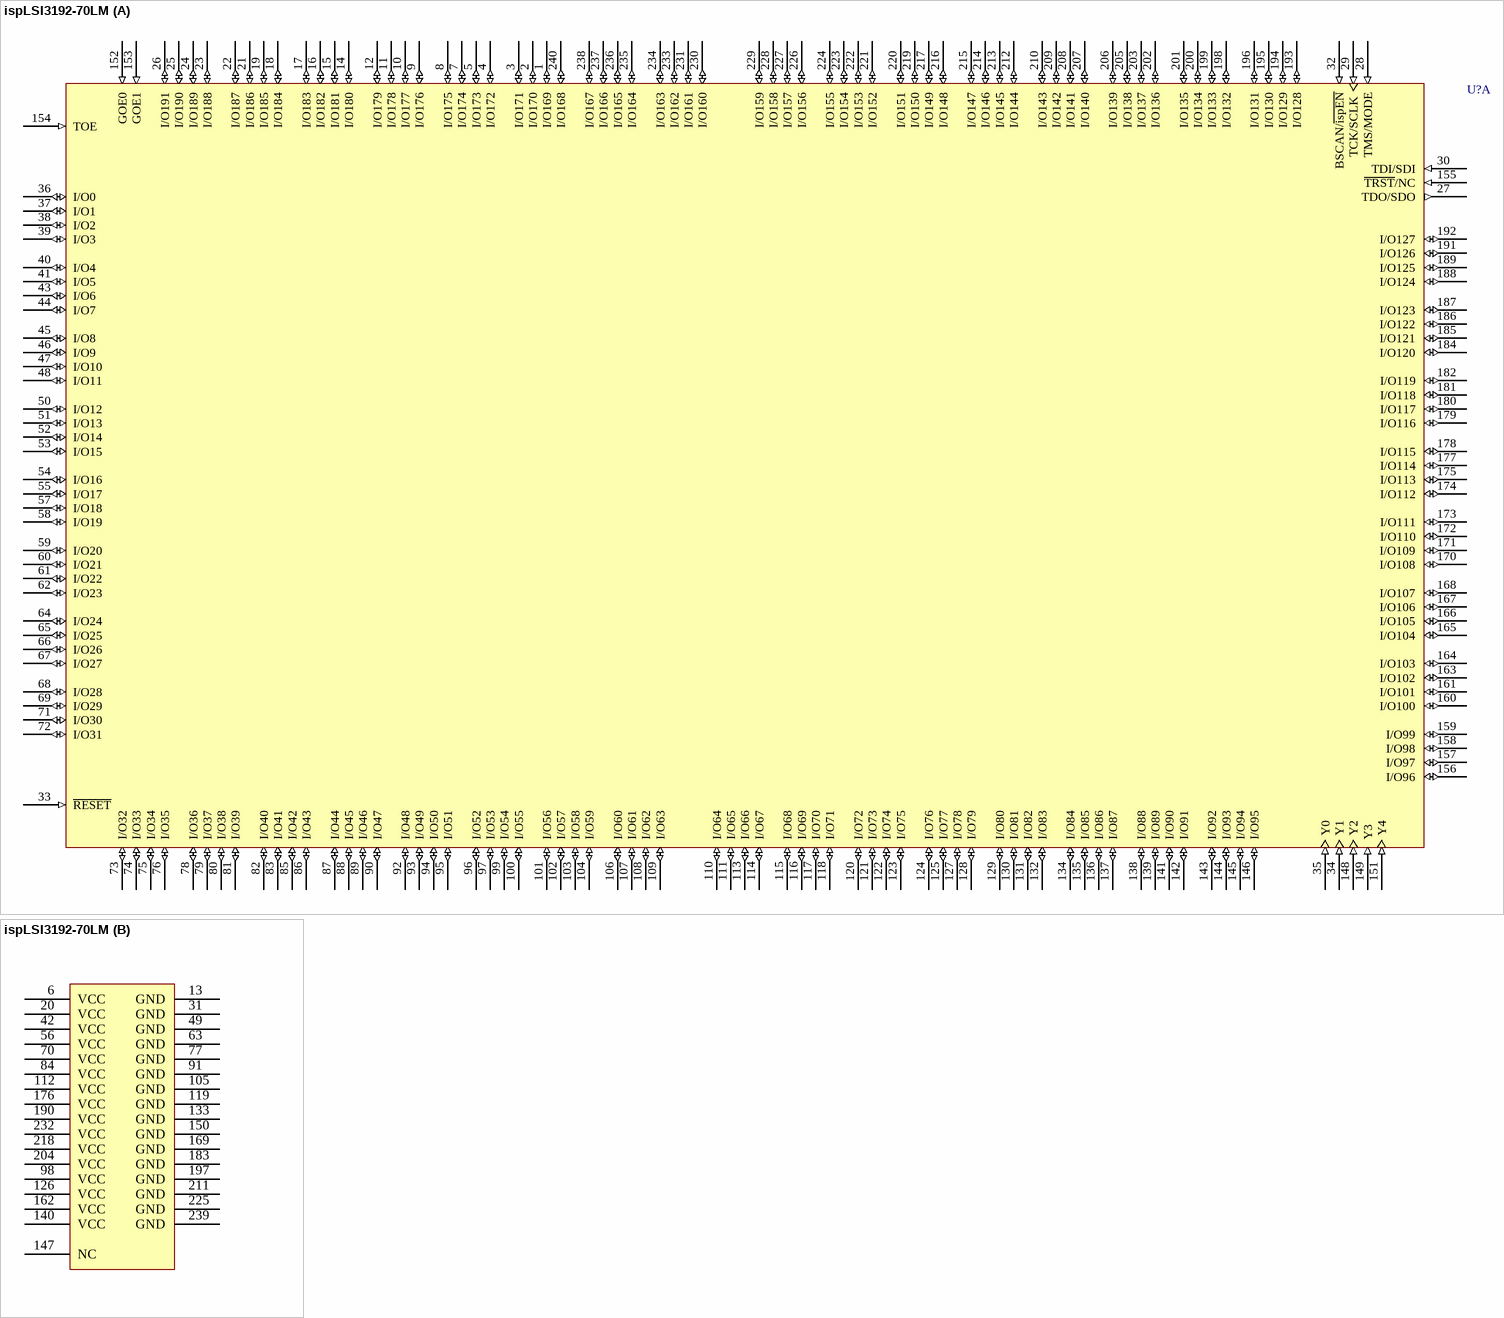
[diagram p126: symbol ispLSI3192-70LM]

## ispLSI3192-70LM
designator U?
High-Density Programmable Logic; Note: Pins 27, 28, 29, 30, 32 and 155 have dual function capability.
footprint MQFP240_N (Shrink QFP, 240-Leads, Body 31.7x31.7mm, Pitch 0.5mm, IPC Medium Density)
footprint MQFP240_L (Shrink QFP, 240-Leads, Body 31.7x31.7mm, Pitch 0.5mm, IPC High Density)
footprint MQFP240_M (Shrink QFP, 240-Leads, Body 31.7x31.7mm, Pitch 0.5mm, IPC Low Density)
3D model 3192-MQFP240 (240-Pin Shrink Quad Flat Pack 0.5 mm Pitch)
part A pins: 1 I/O169 (io), 2 I/O170 (io), 3 I/O171 (io), 4 I/O172 (io), 5 I/O173 (io), 7 I/O174 (io), 8 I/O175 (io), 9 I/O176 (io), 10 I/O177 (io), 11 I/O178 (io), 12 I/O179 (io), 14 I/O180 (io), 15 I/O181 (io), 16 I/O182 (io), 17 I/O183 (io), 18 I/O184 (io), 19 I/O185 (io), 21 I/O186 (io), 22 I/O187 (io), 23 I/O188 (io), 24 I/O189 (io), 25 I/O190 (io), 26 I/O191 (io), 27 TDO/SDO (out), 28 TMS/MODE (in), 29 TCK/SCLK (in), 30 TDI/SDI (in), 32 BSCAN/~{ispEN} (in), 33 ~{RESET} (in), 34 Y1 (in), 35 Y0 (in), 36 I/O0 (io), 37 I/O1 (io), 38 I/O2 (io), 39 I/O3 (io), 40 I/O4 (io), 41 I/O5 (io), 43 I/O6 (io), 44 I/O7 (io), 45 I/O8 (io), 46 I/O9 (io), 47 I/O10 (io), 48 I/O11 (io), 50 I/O12 (io), 51 I/O13 (io), 52 I/O14 (io), 53 I/O15 (io), 54 I/O16 (io), 55 I/O17 (io), 57 I/O18 (io), 58 I/O19 (io), 59 I/O20 (io), 60 I/O21 (io), 61 I/O22 (io), 62 I/O23 (io), 64 I/O24 (io), 65 I/O25 (io), 66 I/O26 (io), 67 I/O27 (io), 68 I/O28 (io), 69 I/O29 (io), 71 I/O30 (io), 72 I/O31 (io), 73 I/O32 (io), 74 I/O33 (io), 75 I/O34 (io), 76 I/O35 (io), 78 I/O36 (io), 79 I/O37 (io), 80 I/O38 (io), 81 I/O39 (io), 82 I/O40 (io), 83 I/O41 (io), 85 I/O42 (io), 86 I/O43 (io), 87 I/O44 (io), 88 I/O45 (io), 89 I/O46 (io), 90 I/O47 (io), 92 I/O48 (io), 93 I/O49 (io), 94 I/O50 (io), 95 I/O51 (io), 96 I/O52 (io), 97 I/O53 (io), 99 I/O54 (io), 100 I/O55 (io), 101 I/O56 (io), 102 I/O57 (io), 103 I/O58 (io), 104 I/O59 (io), 106 I/O60 (io), 107 I/O61 (io), 108 I/O62 (io), 109 I/O63 (io), 110 I/O64 (io), 111 I/O65 (io), 113 I/O66 (io), 114 I/O67 (io), 115 I/O68 (io), 116 I/O69 (io), 117 I/O70 (io), 118 I/O71 (io), 120 I/O72 (io), 121 I/O73 (io), 122 I/O74 (io), 123 I/O75 (io), 124 I/O76 (io), 125 I/O77 (io), 127 I/O78 (io), 128 I/O79 (io), 129 I/O80 (io), 130 I/O81 (io), 131 I/O82 (io), 132 I/O83 (io), 134 I/O84 (io), 135 I/O85 (io), 136 I/O86 (io), 137 I/O87 (io), 138 I/O88 (io), 139 I/O89 (io), 141 I/O90 (io), 142 I/O91 (io), 143 I/O92 (io), 144 I/O93 (io), 145 I/O94 (io), 146 I/O95 (io), 148 Y2 (in), 149 Y3 (in), 151 Y4 (in), 152 GOE0 (in), 153 GOE1 (in), 154 TOE (in), 155 ~{TRST}/NC (in), 156 I/O96 (io), 157 I/O97 (io), 158 I/O98 (io), 159 I/O99 (io), 160 I/O100 (io), 161 I/O101 (io), 163 I/O102 (io), 164 I/O103 (io), 165 I/O104 (io), 166 I/O105 (io), 167 I/O106 (io), 168 I/O107 (io), 170 I/O108 (io), 171 I/O109 (io), 172 I/O110 (io), 173 I/O111 (io), 174 I/O112 (io), 175 I/O113 (io), 177 I/O114 (io), 178 I/O115 (io), 179 I/O116 (io), 180 I/O117 (io), 181 I/O118 (io), 182 I/O119 (io), 184 I/O120 (io), 185 I/O121 (io), 186 I/O122 (io), 187 I/O123 (io), 188 I/O124 (io), 189 I/O125 (io), 191 I/O126 (io), 192 I/O127 (io), 193 I/O128 (io), 194 I/O129 (io), 195 I/O130 (io), 196 I/O131 (io), 198 I/O132 (io), 199 I/O133 (io), 200 I/O134 (io), 201 I/O135 (io), 202 I/O136 (io), 203 I/O137 (io), 205 I/O138 (io), 206 I/O139 (io), 207 I/O140 (io), 208 I/O141 (io), 209 I/O142 (io), 210 I/O143 (io), 212 I/O144 (io), 213 I/O145 (io), 214 I/O146 (io), 215 I/O147 (io), 216 I/O148 (io), 217 I/O149 (io), 219 I/O150 (io), 220 I/O151 (io), 221 I/O152 (io), 222 I/O153 (io), 223 I/O154 (io), 224 I/O155 (io), 226 I/O156 (io), 227 I/O157 (io), 228 I/O158 (io), 229 I/O159 (io), 230 I/O160 (io), 231 I/O161 (io), 233 I/O162 (io), 234 I/O163 (io), 235 I/O164 (io), 236 I/O165 (io), 237 I/O166 (io), 238 I/O167 (io), 240 I/O168 (io)
part B pins: 6 VCC (power), 13 GND (power), 20 VCC (power), 31 GND (power), 42 VCC (power), 49 GND (power), 56 VCC (power), 63 GND (power), 70 VCC (power), 77 GND (power), 84 VCC (power), 91 GND (power), 98 VCC (power), 105 GND (power), 112 VCC (power), 119 GND (power), 126 VCC (power), 133 GND (power), 140 VCC (power), 147 NC, 150 GND (power), 162 VCC (power), 169 GND (power), 176 VCC (power), 183 GND (power), 190 VCC (power), 197 GND (power), 204 VCC (power), 211 GND (power), 218 VCC (power), 225 GND (power), 232 VCC (power), 239 GND (power)

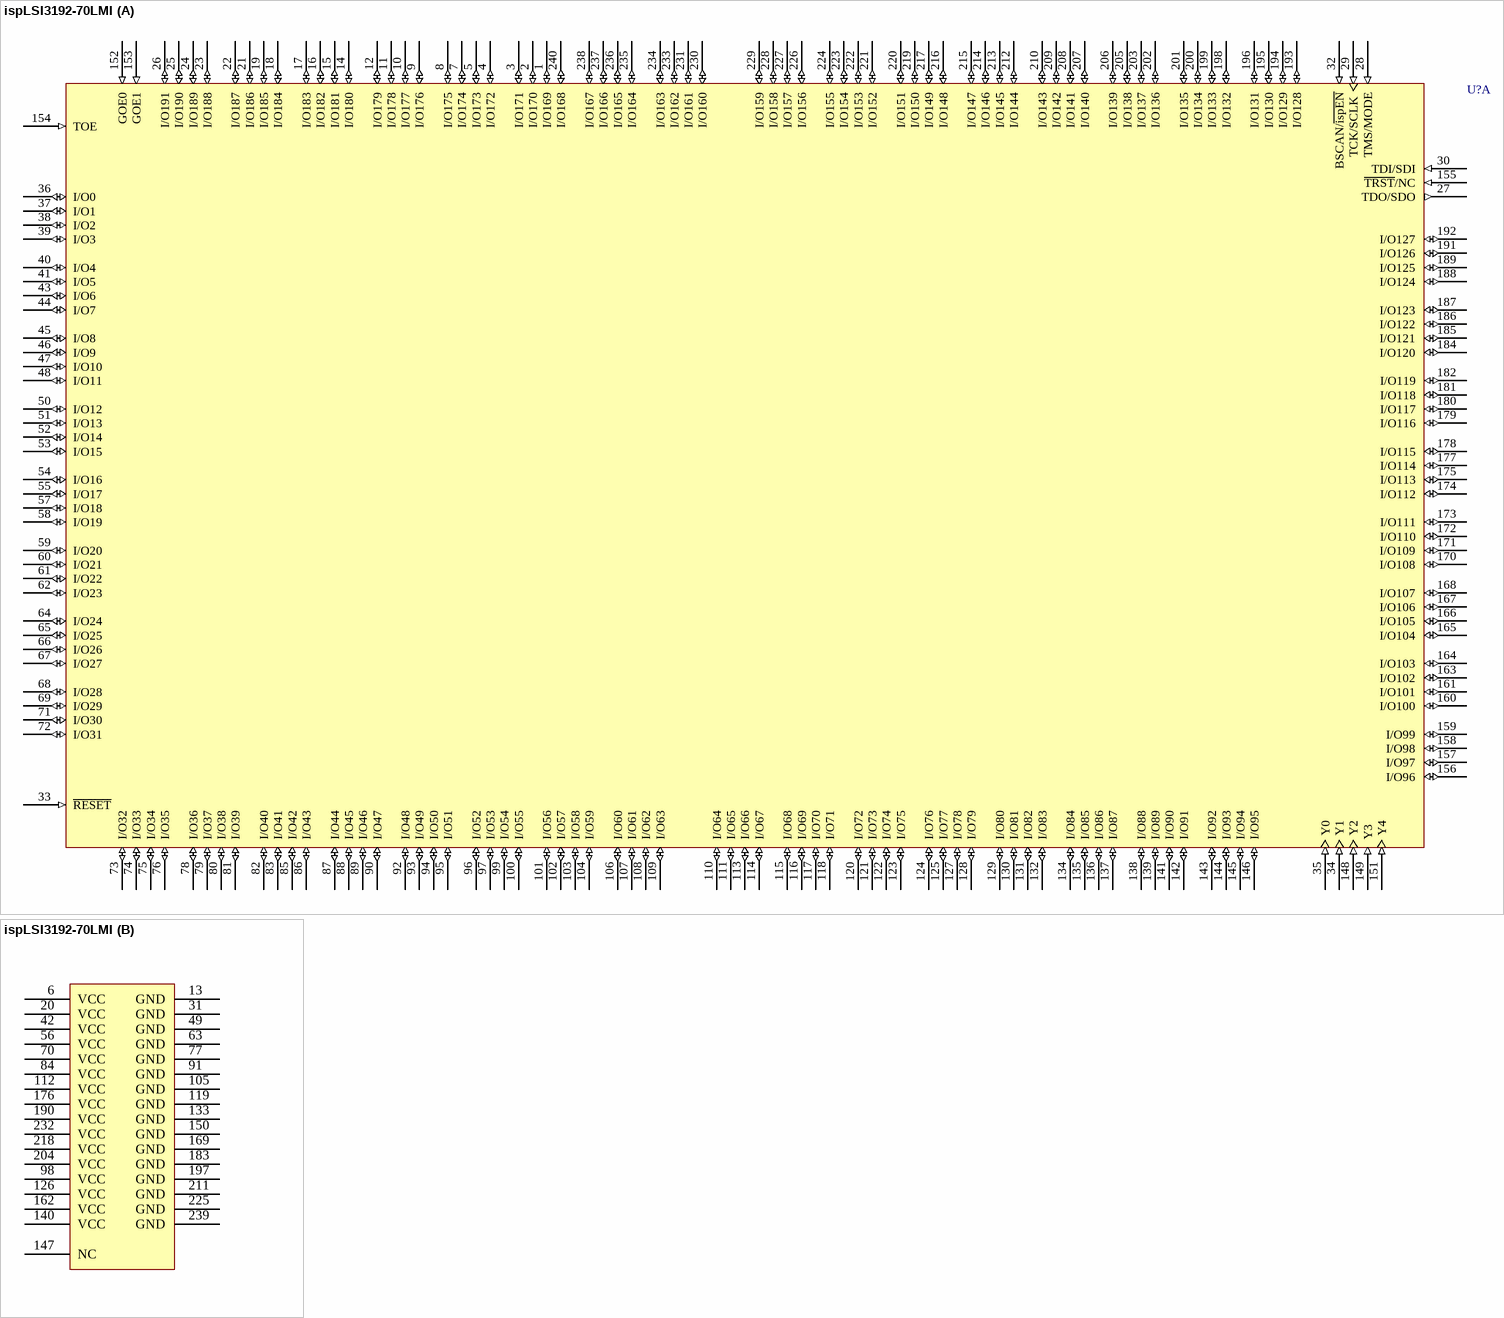
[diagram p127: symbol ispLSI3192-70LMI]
